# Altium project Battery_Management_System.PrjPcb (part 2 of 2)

## Sheet MCU_ADC.SchDoc
size 431 x 279 mm; Date: Not shown in title block; ApprovedBy: Not shown in title block; CheckedBy: Not shown in title block; Author: Not shown in title block; CompanyName: Not shown in title block; Engineer: Not shown in title block; Organization: Not shown in title block; Address1: Not shown in title block; Address2: Not shown in title block; Address3: Not shown in title block; Address4: Not shown in title block; DocumentNumber: 1; Revision: Use project parameter SCH_Rev; SheetNumber: 5; SheetTotal: 8; PageSetup: Record=PageOptions¦CenterHorizontal=True¦CenterVertical=True¦PrintScale=1.00¦XCorrection=1.00¦YCorrection=1.00¦PrintKind=0¦BorderSize=5000000¦LeftOffset=0¦BottomOffset=0¦Orientation=2¦PaperLength=1000¦PaperWidth=1000¦Scale=100¦PaperSource=15¦PrintQuality=600¦MediaType=1¦DitherType=10¦PaperKind=Letter¦PrintScaleMode=1
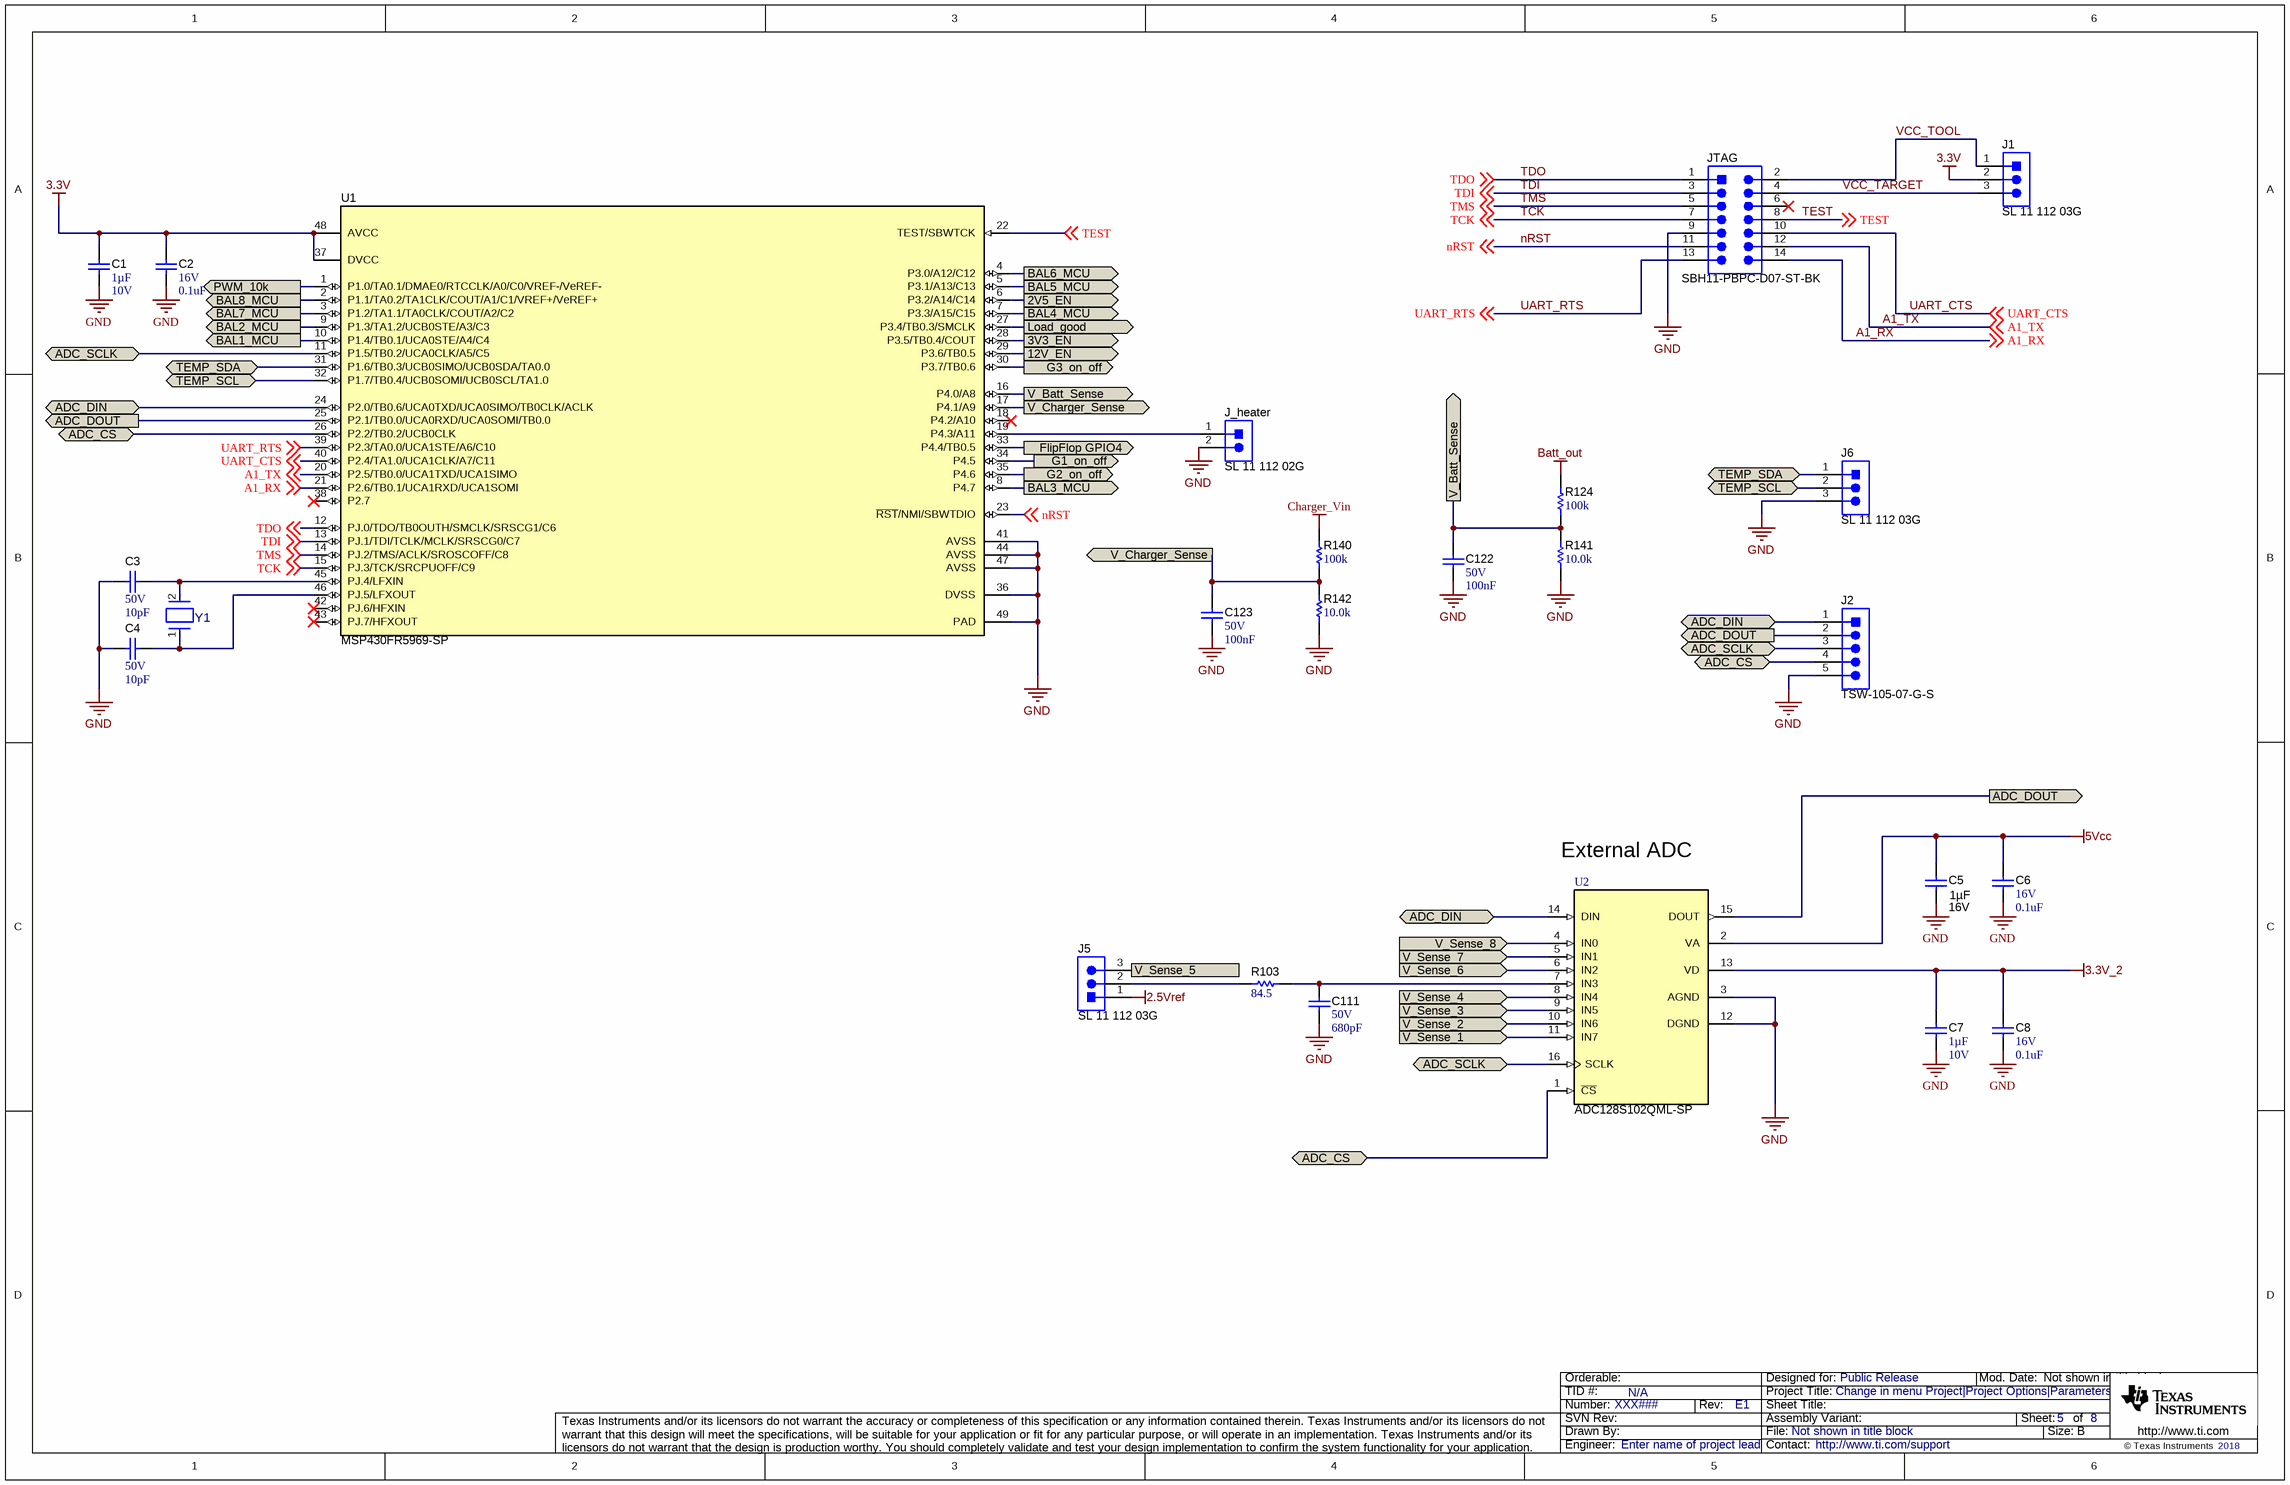
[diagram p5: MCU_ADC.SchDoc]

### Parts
C1  Cap_F: 1µF  VDC_V: 10V  [0805_HV]  (hidden comment: C0805C105K8RACTU)
C2  VDC_V: 16V  ValueDisplayed: 0.1uF  [0805_HV]  (hidden comment: ECPU1C104MA5)
C3  VDC_V: 50V  ValueDisplayed: 10pF  [0603]  (hidden comment: C0603C100J5GACTU)
C4  VDC_V: 50V  ValueDisplayed: 10pF  [0603]  (hidden comment: C0603C100J5GACTU)
C5  Cap_F: 1µF  VDC_V: 16V  [0603]  (hidden comment: CGA3E1X7R1C105K080AC)
C6  VDC_V: 16V  ValueDisplayed: 0.1uF  [0805_HV]  (hidden comment: ECPU1C104MA5)
C7  Cap_F: 1µF  VDC_V: 10V  [0805_HV]  (hidden comment: C0805C105K8RACTU)
C8  VDC_V: 16V  ValueDisplayed: 0.1uF  [0805_HV]  (hidden comment: ECPU1C104MA5)
C111  VDC_V: 50V  ValueDisplayed: 680pF  [0603]  (hidden comment: 06035A681FAT2A)
C122  VDC_V: 50V  Cap_F: 100nF  [0805_HV]  (hidden comment: 08055C104KAT2A)
C123  VDC_V: 50V  Cap_F: 100nF  [0805_HV]  (hidden comment: 08055C104KAT2A)
J1  SL 11 112 03G  [Fischer_SL-11-112-03G]
J2  TSW-105-07-G-S  [TSW-105-07-X-S]
J5  SL 11 112 03G  [Fischer_SL-11-112-03G]
J6  SL 11 112 03G  [Fischer_SL-11-112-03G]
J_heater  SL 11 112 02G  [Fischer_SL-11-112-02G]
JTAG  SBH11-PBPC-D07-ST-BK  [CONN_SBH11-PBPC-D07-ST-BK]
R103  ValueDisplayed: 84.5  [0603]  (hidden comment: RC0603FR-0784R5L)
R124  ValueDisplayed: 100k  [0805_HV]  (hidden comment: RG2012P-104-B-T5)
R140  ValueDisplayed: 100k  [0805_HV]  (hidden comment: RG2012P-104-B-T5)
R141  ValueDisplayed: 10.0k  [0805_HV]  (hidden comment: RG2012P-103-B-T5)
R142  ValueDisplayed: 10.0k  [0805_HV]  (hidden comment: RG2012P-103-B-T5)
U1  PartNumber: MSP430FR5969-SP  [RGZ0048B_NV]  (hidden comment: MSP430FR59691IRGZR)
U2  PartNumber: ADC128S102QML-SP  [NAC0016A_N]  (hidden comment: ADC128S102WGRQV)
Y1  ECS-.327-9-34QCS-TR  [FP-ECS-.327-9-34QCS-TR_SMT_CRYSTAL_3MM2_1MM5-MFG]  (value not drawn)

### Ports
2V5_EN (out), 3V3_EN (out), 12V_EN (out), ADC_CS (bidir), ADC_DIN (bidir), ADC_DOUT (out), ADC_SCLK (bidir), BAL1_MCU (out), BAL2_MCU (out), BAL3_MCU (out), BAL4_MCU (out), BAL5_MCU (out), BAL6_MCU (out), BAL7_MCU (out), BAL8_MCU (out), FlipFlop GPIO4 (out), G1_on_off (out), G2_on_off (out), G3_on_off (out), Load_good (out), PWM_10k (out), TEMP_SCL (bidir), TEMP_SDA (bidir), V_Batt_Sense (out), V_Charger_Sense (out), V_Sense_1 (in), V_Sense_2 (in), V_Sense_3 (in), V_Sense_4 (in), V_Sense_5 (in), V_Sense_6 (in), V_Sense_7 (in), V_Sense_8 (in)

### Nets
2.5Vref: J5.1
3.3V: C1.1 C2.1 J1.2 U1.37(DVCC) U1.48(AVCC)
3.3V_2: C7.1 C8.1 U2.13(VD)
5Vcc: C5.1 C6.1 U2.2(VA)
Batt_out: R124.2
Charger_Vin: R140.2
GND: C1.2 C2.2 C3.2 C4.2 C5.2 C6.2 C7.2 C8.2 C111.2 C122.2 C123.2 J2.5 J6.3 J_heater.2 JTAG.9 R141.1 R142.1 U1.36(DVSS) U1.41(AVSS) U1.44(AVSS) U1.47(AVSS) U1.49(PAD) U2.3(AGND) U2.12(DGND)
2V5_EN: U1.6(P3.2/A14/C14) ; port 2V5_EN
3V3_EN: U1.28(P3.5/TB0.4/COUT) ; port 3V3_EN
12V_EN: U1.29(P3.6/TB0.5) ; port 12V_EN
A1_RX: JTAG.14 U1.21(P2.6/TB0.1/UCA1RXD/UCA1SOMI) ; off-sheet A1_RX
A1_TX: JTAG.12 U1.20(P2.5/TB0.0/UCA1TXD/UCA1SIMO) ; off-sheet A1_TX
ADC_CS: J2.4 U1.26(P2.2/TB0.2/UCB0CLK) U2.1(~{CS}) ; port ADC_CS
ADC_DIN: J2.1 U1.24(P2.0/TB0.6/UCA0TXD/UCA0SIMO/TB0CLK/ACLK) U2.14(DIN) ; port ADC_DIN
ADC_DOUT: J2.2 U1.25(P2.1/TB0.0/UCA0RXD/UCA0SOMI/TB0.0) U2.15(DOUT) ; port ADC_DOUT
ADC_SCLK: J2.3 U1.11(P1.5/TB0.2/UCA0CLK/A5/C5) U2.16(SCLK) ; port ADC_SCLK
BAL1_MCU: U1.10(P1.4/TB0.1/UCA0STE/A4/C4) ; port BAL1_MCU
BAL2_MCU: U1.9(P1.3/TA1.2/UCB0STE/A3/C3) ; port BAL2_MCU
BAL3_MCU: U1.8(P4.7) ; port BAL3_MCU
BAL4_MCU: U1.7(P3.3/A15/C15) ; port BAL4_MCU
BAL5_MCU: U1.5(P3.1/A13/C13) ; port BAL5_MCU
BAL6_MCU: U1.4(P3.0/A12/C12) ; port BAL6_MCU
BAL7_MCU: U1.3(P1.2/TA1.1/TA0CLK/COUT/A2/C2) ; port BAL7_MCU
BAL8_MCU: U1.2(P1.1/TA0.2/TA1CLK/COUT/A1/C1/VREF+/VeREF+) ; port BAL8_MCU
FlipFlop GPIO4: U1.33(P4.4/TB0.5) ; port FlipFlop GPIO4
G1_on_off: U1.34(P4.5) ; port G1_on_off
G2_on_off: U1.35(P4.6) ; port G2_on_off
G3_on_off: U1.30(P3.7/TB0.6) ; port G3_on_off
Load_good: U1.27(P3.4/TB0.3/SMCLK) ; port Load_good
nRST: JTAG.11 U1.23(~{RST}/NMI/SBWTDIO) ; off-sheet nRST
PWM_10k: U1.1(P1.0/TA0.1/DMAE0/RTCCLK/A0/C0/VREF-/VeREF-) ; port PWM_10k
TCK: JTAG.7 U1.15(PJ.3/TCK/SRCPUOFF/C9) ; off-sheet TCK
TDI: JTAG.3 U1.13(PJ.1/TDI/TCLK/MCLK/SRSCG0/C7) ; off-sheet TDI
TDO: JTAG.1 U1.12(PJ.0/TDO/TB0OUTH/SMCLK/SRSCG1/C6) ; off-sheet TDO
TEMP_SCL: J6.2 U1.32(P1.7/TB0.4/UCB0SOMI/UCB0SCL/TA1.0) ; port TEMP_SCL
TEMP_SDA: J6.1 U1.31(P1.6/TB0.3/UCB0SIMO/UCB0SDA/TA0.0) ; port TEMP_SDA
TEST: JTAG.8 U1.22(TEST/SBWTCK) ; off-sheet TEST
TMS: JTAG.5 U1.14(PJ.2/TMS/ACLK/SROSCOFF/C8) ; off-sheet TMS
UART_CTS: JTAG.10 U1.40(P2.4/TA1.0/UCA1CLK/A7/C11) ; off-sheet UART_CTS
UART_RTS: JTAG.13 U1.39(P2.3/TA0.0/UCA1STE/A6/C10) ; off-sheet UART_RTS
V_Batt_Sense: C122.1 R124.1 R141.2 U1.16(P4.0/A8) ; port V_Batt_Sense
V_Charger_Sense: C123.1 R140.1 R142.2 U1.17(P4.1/A9) ; port V_Charger_Sense
V_Sense_1: U2.11(IN7) ; port V_Sense_1
V_Sense_2: U2.10(IN6) ; port V_Sense_2
V_Sense_3: U2.9(IN5) ; port V_Sense_3
V_Sense_4: U2.8(IN4) ; port V_Sense_4
V_Sense_5: J5.3 ; port V_Sense_5
V_Sense_6: U2.6(IN2) ; port V_Sense_6
V_Sense_7: U2.5(IN1) ; port V_Sense_7
V_Sense_8: U2.4(IN0) ; port V_Sense_8
VCC_TARGET: J1.3 JTAG.4
VCC_TOOL: J1.1 JTAG.2
NetC3_1: C3.1 U1.45(PJ.4/LFXIN) Y1.2(Out/In)
NetC4_1: C4.1 U1.46(PJ.5/LFXOUT) Y1.1(In/Out)
NetC111_1: C111.1 R103.2 U2.7(IN3)
NetJ5_2: J5.2 R103.1
NetJ_heater_1: J_heater.1 U1.19(P4.3/A11)

Not connected (* = marked no-connect by the designer): JTAG 6*; U1 18(P4.2/A10)* 38(P2.7)* 42(PJ.6/HFXIN)* 43(PJ.7/HFXOUT)*

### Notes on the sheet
- External ADC

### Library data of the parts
C1 C7 = CMP-0007731-1: CAP, CERM, 1 uF, 10 V, +/- 10%, X7R, 0805; Manufacturer: Kemet; TaMin_C: -55°C; ESR_ohm: 15m; Polarized: N; SizeAreaWB_mm2: 6.75; Value1: 0.015 ohm; U/M: EA; Value: 1uF; TaMax_C: 125°C; SizeZ_mm: 1.45; SizeX_mm: 2; SizeY_mm: 1.25; Cap_Case: 0805; SizeArea_mm2: 2.5; IRMS_A: 8.19A; AEC Category: Q200
C2 C6 C8 = CMP-0012474-2: CAP, Film, 0.1 uF, 16 V, +/- 20%, 0805 SMD; Manufacturer: Panasonic; TaMin_C: -40°C; Polarized: N; SizeAreaWB_mm2: 6.75; Value1: Unknown; U/M: EA; Value: 0.1uF; TaMax_C: 85°C; SizeZ_mm: 1.45; SizeX_mm: 2; SizeY_mm: 1.25; Cap_Case: 0805; SizeArea_mm2: 2.5; Cap_F: 100nF; AEC Category: Q200
C3 C4 = CMP-0006839-1: CAP, CERM, 10 pF, 50 V, +/- 5%, C0G/NP0, 0603; Manufacturer: Kemet; TaMin_C: -55°C; Polarized: N; SizeAreaWB_mm2: 4.68; Value1: Unknown; U/M: EA; Value: 10pF; TaMax_C: 125°C; SizeZ_mm: 1; SizeX_mm: 1.6; SizeY_mm: 0.8; SizeArea_mm2: 1.28; AEC Category: Q200
C5 = CMP-0079607-1: CAP, CERM, 1 µF, 16 V,+/- 10%, X7R, AEC-Q200 Grade 1, 0603; Manufacturer: TDK; TaMin_C: -55°C; Polarized: N; SizeAreaWB_mm2: 4.68; U/M: EA; Value: 1uF; TaMax_C: 125°C; SizeZ_mm: 1; SizeX_mm: 1.6; SizeY_mm: 0.8; SizeArea_mm2: 1.28; AEC Qualified: Y; AEC Category: Q200
C111 = CMP-0006797-3: CAP, CERM, 680 pF, 50 V, +/- 1%, C0G/NP0, 0603; Manufacturer: AVX; TaMin_C: -55°C; Polarized: N; SizeAreaWB_mm2: 4.68; Value1: Unknown; U/M: EA; Value: 680pF; TaMax_C: 125°C; SizeZ_mm: 1; SizeX_mm: 1.6; SizeY_mm: 0.8; SizeArea_mm2: 1.28; AEC Category: Q200
C122 C123 = CMP-0007632-1: CAP, CERM, 0.1 uF, 50 V, +/- 10%, X7R, 0805; Manufacturer: AVX; TaMin_C: -55°C; ESR_ohm: 24m; Polarized: N; SizeAreaWB_mm2: 6.75; Value1: 0.024 ohm; U/M: EA; Value: 0.1uF; TaMax_C: 125°C; SizeZ_mm: 1.45; SizeX_mm: 2; SizeY_mm: 1.25; Cap_Case: 0805; SizeArea_mm2: 2.5; AEC Category: Q200
J1 J5 J6 = CMP-0075048-1: Header, 2.54mm, 3x1, Gold, TH; Manufacturer: Fischer Elektronik; CT: False; CNHeader: True
J2 = CMP-0075411-1: Header, 100mil, 5x1, Gold, TH; Manufacturer: Samtec; Pitch_mm: 2.54; Cert_VDE: N; Gender: Male; Cert_CSA: Y; Voltage_V: 550V; Green_REACh: Passed; Current_A: 6.3A; CT: False; Green_Lifecycle: Active; Row_Count: 1; CNHeader: True
J_heater = CMP-0075049-1: Header, 2.54mm, 2x1, Gold, TH; Manufacturer: Fischer Elektronik; CT: False; CNHeader: True
JTAG = CMP-0054695-2: Header (shrouded), 100 mil, 7x2, Gold, TH; Manufacturer: Sullins Connector Solutions; Green_REACh: Incomplete; Green_Lifecycle: Not Set
R103 = CMP-0023298-5: RES, 84.5, 1%, 0.1 W, 0603; Manufacturer: Yageo; Power_W: 100mW; TempCo: 100 ppm/C; Value_Code: 84R5; Value: 84.5; EIA_Code: E96; SizeX_mm: 1.6; SizeY_mm: 0.8; SizeZ_mm: 1; Value2: 0.1W; SizeArea_mm2: 1.28; AEC Qualified: N; VDC_V: 75V; AEC Category: Q200; SizeAreaWB_mm2: 4.68
R124 R140 = CMP-0018857-2: RES, 100 k, 0.1%, 0.125 W, 0805; Manufacturer: Susumu Co Ltd; Power_W: 125mW; TempCo: 25 ppm/C; U/M: EA; Value: 100k; EIA_Code: E192; SizeX_mm: 2; SizeY_mm: 1.25; SizeZ_mm: 1.45; Value2: 0.125W; SizeArea_mm2: 2.5; VDC_V: 100V; AEC Category: Q200
R141 R142 = CMP-0018856-2: RES, 10.0 k, 0.1%, 0.125 W, 0805; Manufacturer: Susumu Co Ltd; Power_W: 125mW; TempCo: 25 ppm/C; Value_Code: 10k0; U/M: EA; Value: 10.0k; EIA_Code: E192; Res_ohm: 10k; SizeX_mm: 2; SizeY_mm: 1.25; SizeZ_mm: 1.45; Value2: 0.125W; SizeArea_mm2: 2.5; VDC_V: 100V; AEC Category: Q200
U1 = CMP-0076614-1: MSP430FR59691 16 MHz Ultra-Low-Power Microcontroller featuring 64 KB FRAM, 2 KB SRAM, 40 IO, RGZ0048B (VQFN-48); Manufacturer: Texas Instruments; Alternate PartNumber: MSP430FR59691IRGZT; SizeAreaWB_mm2: 81.0; SizeArea_mm2: 49.0; SizeZ_mm: 1.0; SizeY_mm: 7.0; U/M: EA; CompType: IC
U2 = CMP-0067762-2: 3V LVDS Quad CMOS Differential Line Driver, NAC0016A (CFP-16); Manufacturer: Texas Instruments; CompType: ADC IC; High-Reliability: Y; AEC Category: Q200; AEC Qualified: N; SizeAreaWB_mm2: 295.5; SizeArea_mm2: 103.2; SizeX_mm: 10.41; SizeY_mm: 9.91; SizeZ_mm: 2.33
Y1 = CMP-0089623-1: 32.768kHz ±10ppm Crystal 9pF 80 kOhms 2-SMD, No Lead , Automotive AEC-Q200; Manufacturer: ECS Inc.; AEC Grade: Grade 1; Esr: 70k; SizeZ_mm: 0.9mm; AEC Qualified: Yes

## Sheet Balancer.SchDoc
size 431 x 279 mm; Date: Not shown in title block; ApprovedBy: Not shown in title block; CheckedBy: Not shown in title block; Author: Not shown in title block; CompanyName: Not shown in title block; Engineer: Not shown in title block; Organization: Not shown in title block; Address1: Not shown in title block; Address2: Not shown in title block; Address3: Not shown in title block; Address4: Not shown in title block; DocumentNumber: 1; Revision: Use project parameter SCH_Rev; SheetNumber: 6; SheetTotal: 8; PageSetup: Record=PageOptions¦CenterHorizontal=True¦CenterVertical=True¦PrintScale=1.00¦XCorrection=1.00¦YCorrection=1.00¦PrintKind=0¦BorderSize=5000000¦LeftOffset=0¦BottomOffset=0¦Orientation=2¦PaperLength=1000¦PaperWidth=1000¦Scale=100¦PaperSource=15¦PrintQuality=600¦MediaType=1¦DitherType=10¦PaperKind=Letter¦PrintScaleMode=1
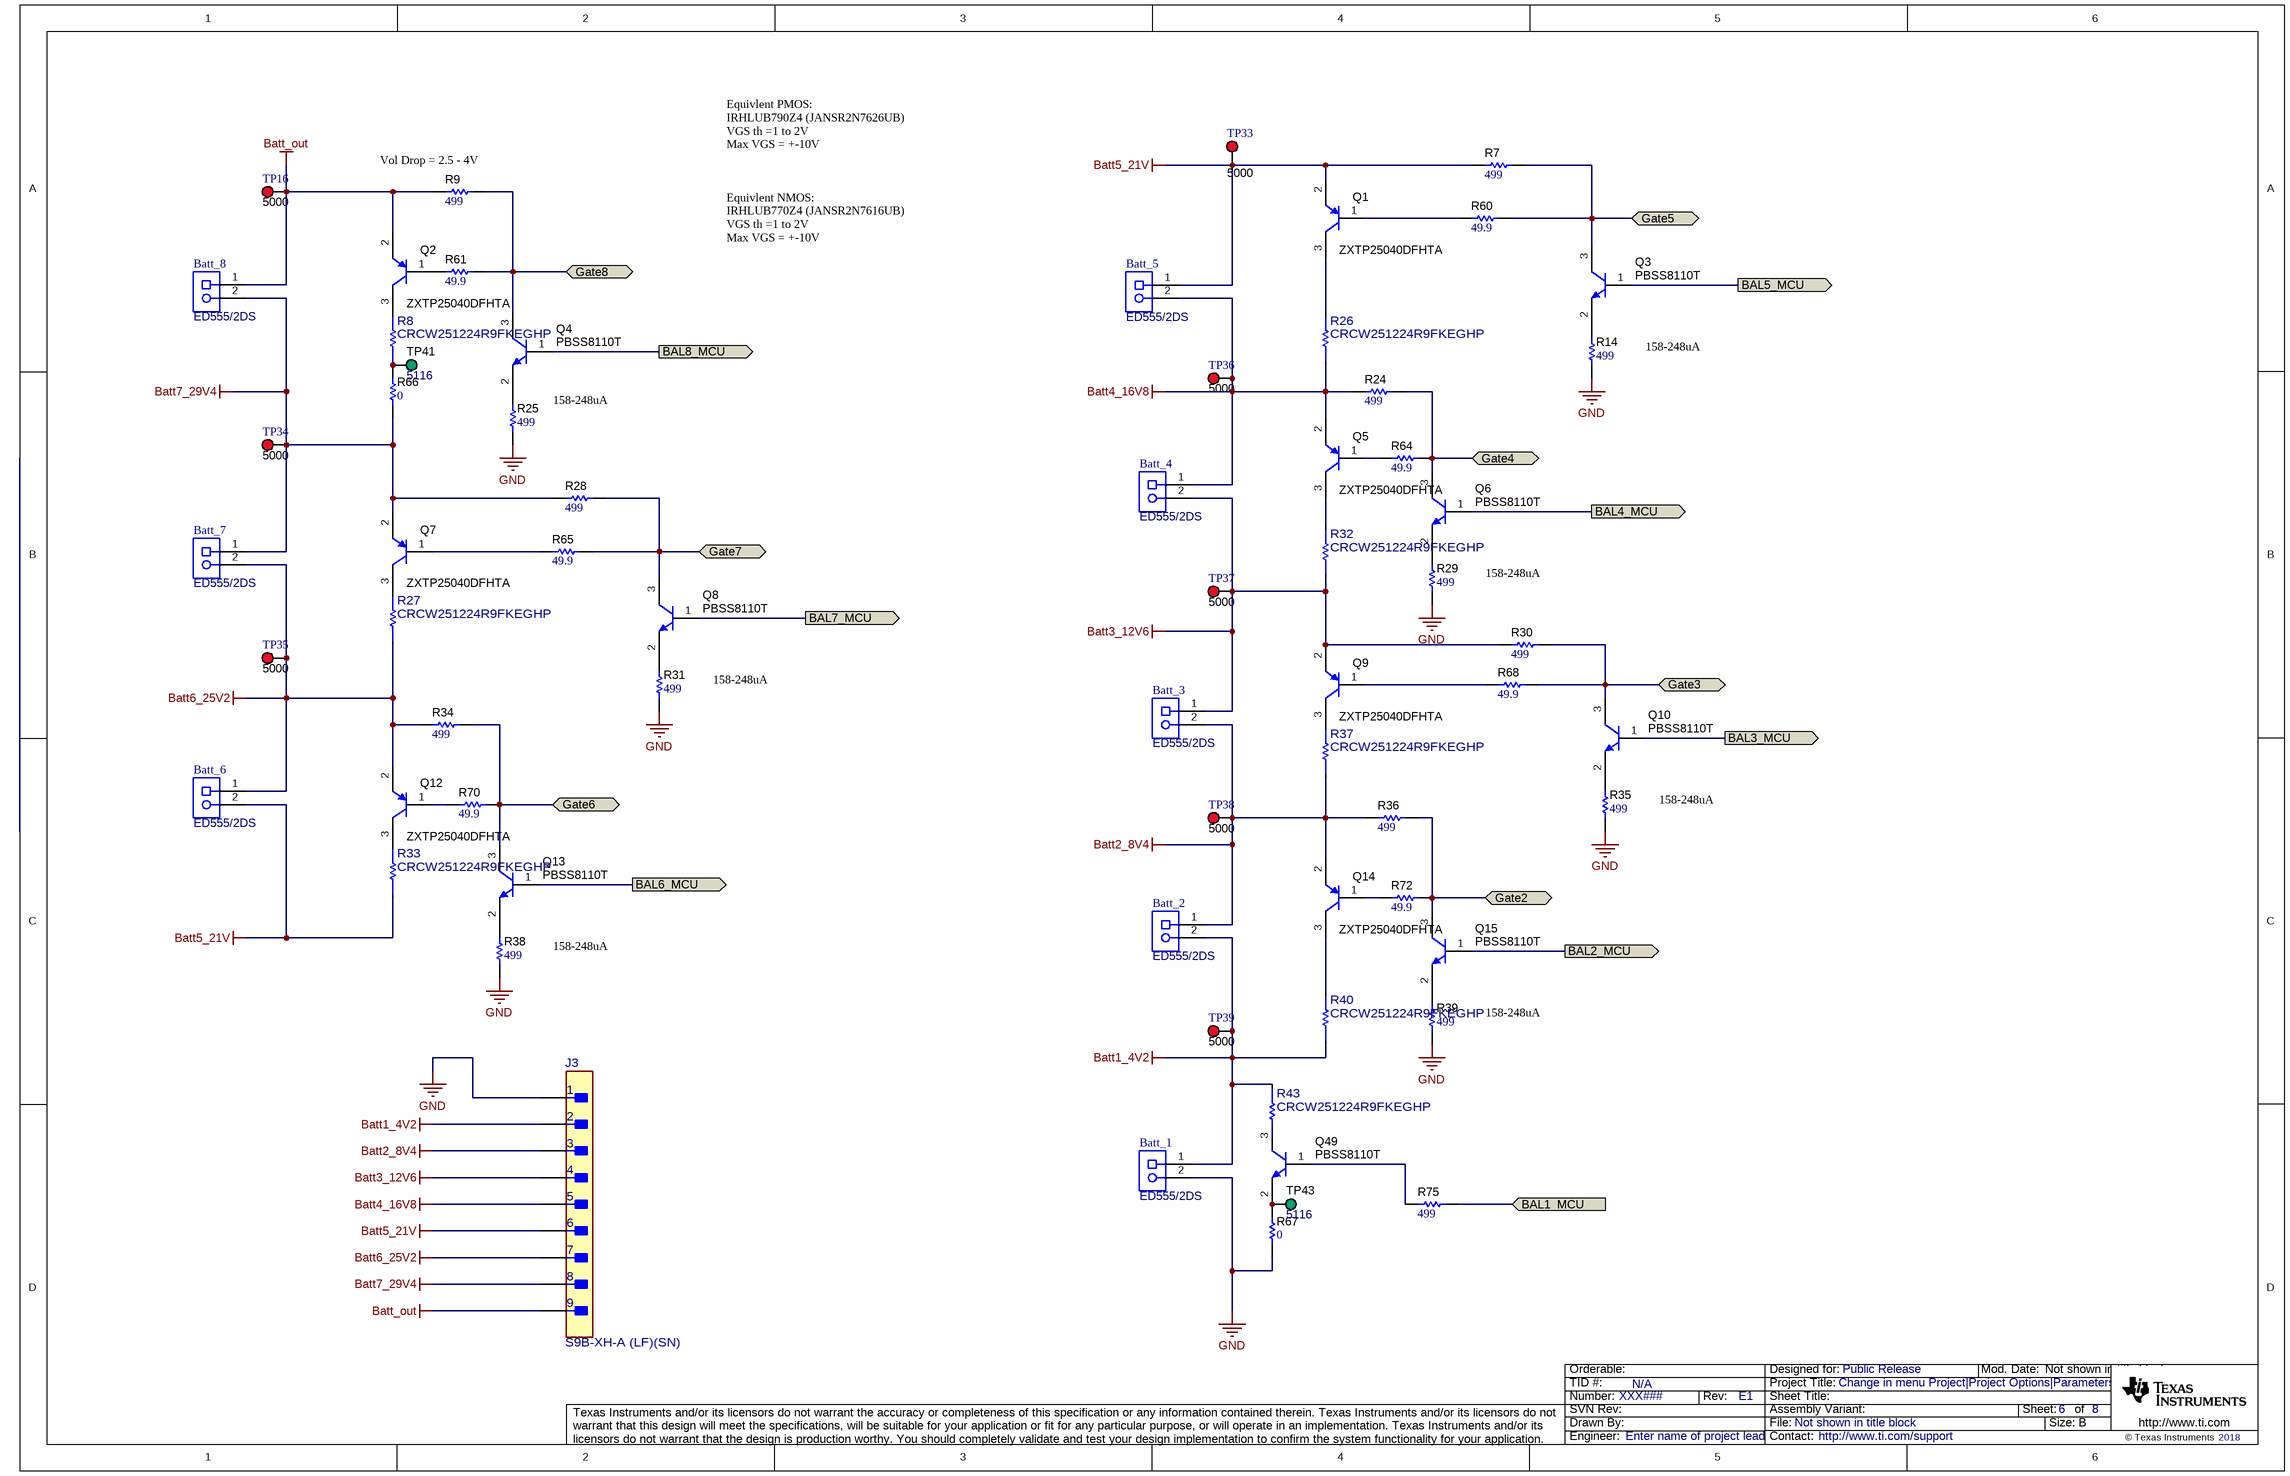
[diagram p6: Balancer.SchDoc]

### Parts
Batt_1  ED555/2DS  [TERM_BLK_ED555-2DS]
Batt_2  ED555/2DS  [TERM_BLK_ED555-2DS]
Batt_3  ED555/2DS  [TERM_BLK_ED555-2DS]
Batt_4  ED555/2DS  [TERM_BLK_ED555-2DS]
Batt_5  ED555/2DS  [TERM_BLK_ED555-2DS]
Batt_6  ED555/2DS  [TERM_BLK_ED555-2DS]
Batt_7  ED555/2DS  [TERM_BLK_ED555-2DS]
Batt_8  ED555/2DS  [TERM_BLK_ED555-2DS]
J3  S9B-XH-A (LF)(SN)  [FP-S9B-XH-A (LF)(SN)_CONN_FFC_9P-MFG]
Q1  ZXTP25040DFHTA  [SOT-23]
Q2  ZXTP25040DFHTA  [SOT-23]
Q3  PBSS8110T  [SOT-23]
Q4  PBSS8110T  [SOT-23]
Q5  ZXTP25040DFHTA  [SOT-23]
Q6  PBSS8110T  [SOT-23]
Q7  ZXTP25040DFHTA  [SOT-23]
Q8  PBSS8110T  [SOT-23]
Q9  ZXTP25040DFHTA  [SOT-23]
Q10  PBSS8110T  [SOT-23]
Q12  ZXTP25040DFHTA  [SOT-23]
Q13  PBSS8110T  [SOT-23]
Q14  ZXTP25040DFHTA  [SOT-23]
Q15  PBSS8110T  [SOT-23]
Q49  PBSS8110T  [SOT-23]
R7  ValueDisplayed: 499  [0805_HV]  (hidden comment: CRCW0805499RFKEA)
R8  CRCW251224R9FKEGHP  [FP-CRCW251224R9FKEGHP_2512-MFG]
R9  ValueDisplayed: 499  [0805_HV]  (hidden comment: CRCW0805499RFKEA)
R14  ValueDisplayed: 499  [0805_HV]  (hidden comment: CRCW0805499RFKEA)
R24  ValueDisplayed: 499  [0805_HV]  (hidden comment: CRCW0805499RFKEA)
R25  ValueDisplayed: 499  [0805_HV]  (hidden comment: CRCW0805499RFKEA)
R26  CRCW251224R9FKEGHP  [FP-CRCW251224R9FKEGHP_2512-MFG]
R27  CRCW251224R9FKEGHP  [FP-CRCW251224R9FKEGHP_2512-MFG]
R28  ValueDisplayed: 499  [0805_HV]  (hidden comment: CRCW0805499RFKEA)
R29  ValueDisplayed: 499  [0805_HV]  (hidden comment: CRCW0805499RFKEA)
R30  ValueDisplayed: 499  [0805_HV]  (hidden comment: CRCW0805499RFKEA)
R31  ValueDisplayed: 499  [0805_HV]  (hidden comment: CRCW0805499RFKEA)
R32  CRCW251224R9FKEGHP  [FP-CRCW251224R9FKEGHP_2512-MFG]
R33  CRCW251224R9FKEGHP  [FP-CRCW251224R9FKEGHP_2512-MFG]
R34  ValueDisplayed: 499  [0805_HV]  (hidden comment: CRCW0805499RFKEA)
R35  ValueDisplayed: 499  [0805_HV]  (hidden comment: CRCW0805499RFKEA)
R36  ValueDisplayed: 499  [0805_HV]  (hidden comment: CRCW0805499RFKEA)
R37  CRCW251224R9FKEGHP  [FP-CRCW251224R9FKEGHP_2512-MFG]
R38  ValueDisplayed: 499  [0805_HV]  (hidden comment: CRCW0805499RFKEA)
R39  ValueDisplayed: 499  [0805_HV]  (hidden comment: CRCW0805499RFKEA)
R40  CRCW251224R9FKEGHP  [FP-CRCW251224R9FKEGHP_2512-MFG]
R43  CRCW251224R9FKEGHP  [FP-CRCW251224R9FKEGHP_2512-MFG]
R60  ValueDisplayed: 49.9  [0805_HV]  (hidden comment: M55342K06B49D9T)
R61  ValueDisplayed: 49.9  [0805_HV]  (hidden comment: M55342K06B49D9T)
R64  ValueDisplayed: 49.9  [0805_HV]  (hidden comment: M55342K06B49D9T)
R65  ValueDisplayed: 49.9  [0805_HV]  (hidden comment: M55342K06B49D9T)
R66  ValueDisplayed: 0  [0805_HV]  (hidden comment: MCR10EZHJ000)
R67  ValueDisplayed: 0  [0805_HV]  (hidden comment: MCR10EZHJ000)
R68  ValueDisplayed: 49.9  [0805_HV]  (hidden comment: M55342K06B49D9T)
R70  ValueDisplayed: 49.9  [0805_HV]  (hidden comment: M55342K06B49D9T)
R72  ValueDisplayed: 49.9  [0805_HV]  (hidden comment: M55342K06B49D9T)
R75  ValueDisplayed: 499  [0805_HV]  (hidden comment: CRCW0805499RFKEA)
TP16  5000  [Keystone5000]
TP33  5000  [Keystone5000]
TP34  5000  [Keystone5000]
TP35  5000  [Keystone5000]
TP36  5000  [Keystone5000]
TP37  5000  [Keystone5000]
TP38  5000  [Keystone5000]
TP39  5000  [Keystone5000]
TP41  5116  [Keystone_5116]
TP43  5116  [Keystone_5116]

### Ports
BAL1_MCU (in), BAL2_MCU (out), BAL3_MCU (out), BAL4_MCU (out), BAL5_MCU (out), BAL6_MCU (out), BAL7_MCU (out), BAL8_MCU (out), Gate2 (bidir), Gate3 (bidir), Gate4 (bidir), Gate5 (bidir), Gate6 (bidir), Gate7 (bidir), Gate8 (bidir)

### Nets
Batt1_4V2: Batt_1.1 Batt_2.2 J3.2 R40.1 R43.2 TP39.1
Batt2_8V4: Batt_2.1 Batt_3.2 J3.3 Q14.2(E) R36.1 R37.1 TP38.1
Batt3_12V6: Batt_3.1 Batt_4.2 J3.4 Q9.2(E) R30.1 R32.1 TP37.1
Batt4_16V8: Batt_4.1 Batt_5.2 J3.5 Q5.2(E) R24.1 R26.1 TP36.1
Batt5_21V: Batt_5.1 Batt_6.2 J3.6 Q1.2(E) R7.1 R33.1 TP33.1
Batt6_25V2: Batt_6.1 Batt_7.2 J3.7 Q12.2(E) R27.1 R34.1 TP35.1
Batt7_29V4: Batt_7.1 Batt_8.2 J3.8 Q7.2(E) R28.1 R66.2 TP34.1
Batt_out: Batt_8.1 J3.9 Q2.2(E) R9.1 TP16.1
GND: Batt_1.2 J3.1 R14.1 R25.1 R29.1 R31.1 R35.1 R38.1 R39.1 R67.2
BAL1_MCU: R75.2 ; port BAL1_MCU
BAL2_MCU: Q15.1(B) ; port BAL2_MCU
BAL3_MCU: Q10.1(B) ; port BAL3_MCU
BAL4_MCU: Q6.1(B) ; port BAL4_MCU
BAL5_MCU: Q3.1(B) ; port BAL5_MCU
BAL6_MCU: Q13.1(B) ; port BAL6_MCU
BAL7_MCU: Q8.1(B) ; port BAL7_MCU
BAL8_MCU: Q4.1(B) ; port BAL8_MCU
Gate2: Q15.3(C) R36.2 R72.2 ; port Gate2
Gate3: Q10.3(C) R30.2 R68.2 ; port Gate3
Gate4: Q6.3(C) R24.2 R64.2 ; port Gate4
Gate5: Q3.3(C) R7.2 R60.2 ; port Gate5
Gate6: Q13.3(C) R34.2 R70.2 ; port Gate6
Gate7: Q8.3(C) R28.2 R65.2 ; port Gate7
Gate8: Q4.3(C) R9.2 R61.2 ; port Gate8
NetQ1_1: Q1.1(B) R60.1
NetQ1_3: Q1.3(C) R26.2
NetQ2_1: Q2.1(B) R61.1
NetQ2_3: Q2.3(C) R8.2
NetQ3_2: Q3.2(E) R14.2
NetQ4_2: Q4.2(E) R25.2
NetQ5_1: Q5.1(B) R64.1
NetQ5_3: Q5.3(C) R32.2
NetQ6_2: Q6.2(E) R29.2
NetQ7_1: Q7.1(B) R65.1
NetQ7_3: Q7.3(C) R27.2
NetQ8_2: Q8.2(E) R31.2
NetQ9_1: Q9.1(B) R68.1
NetQ9_3: Q9.3(C) R37.2
NetQ10_2: Q10.2(E) R35.2
NetQ12_1: Q12.1(B) R70.1
NetQ12_3: Q12.3(C) R33.2
NetQ13_2: Q13.2(E) R38.2
NetQ14_1: Q14.1(B) R72.1
NetQ14_3: Q14.3(C) R40.2
NetQ15_2: Q15.2(E) R39.2
NetQ49_1: Q49.1(B) R75.1
NetQ49_2: Q49.2(E) R67.1 TP43.1
NetQ49_3: Q49.3(C) R43.1
NetR8_1: R8.1 R66.1 TP41.1

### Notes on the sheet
- (near R9) Vol Drop = 2.5 - 4V
- Equivlent PMOS:
  IRHLUB790Z4 (JANSR2N7626UB)
  VGS th =1 to 2V
  Max VGS = +-10V
- Equivlent NMOS:
  IRHLUB770Z4 (JANSR2N7616UB)
  VGS th =1 to 2V
  Max VGS = +-10V
- 158-248uA

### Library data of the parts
Batt_1-Batt_8 = CMP-0074913-1: Terminal Block, 3.5mm Pitch, 2x1, TH; Manufacturer: On-Shore Technology; Cert_VDE: Y; CNHeader: False; Current_A: 6A; Green_Lifecycle: Active; Shrouded: N; Gender: Female; Green_REACh: Passed; Voltage_V: 150V; Row_Count: 1; Pitch_mm: 3.5; ContactFinish: Brass; CT: True
J3 = CMP-0097746-1: Connector Header Through Hole, Right Angle 9 position 0.098" (2.50mm); Manufacturer: JST; DUT-Pitch_mm: 2.5mm; Current_A: 3A; Conn Gender: Male; Row_Count: 1; SizeZ_mm: 6.1mm; Is Female: yes; AEC Qualified: No; Voltage_V: 250V; ContactFinish: Tin,Copper
Q1 Q2 Q5 Q7 Q9 Q12 Q14 = CMP-0000353-2: Transistor, PNP, 40 V, 3 A, SOT-23; Manufacturer: Diodes Inc.; TaMax_C: 150°C; Value2: 900; Value1: 3 A; Vcesat1_V: 170mV; SizeX_mm: 2.5; SizeY_mm: 3; TaMin_C: -55°C; IcRated_A: 3A; CompType: BJT; SizeZ_mm: 1.1; AEC Qualified: N; Value: 40 V; SizeArea_mm2: 7.5; NPN: 0; Vceo_V: 40V; PNP: 1; AEC Category: Q101; SizeAreaWB_mm2: 14; U/M: EA
Q3 Q4 Q6 Q8 Q10 Q13 Q15 Q49 = CMP-0000451-1: Transistor, NPN, 100 V, 1 A, SOT-23; Manufacturer: NXP Semiconductor; TaMax_C: 150°C; Value2: 500; Value1: 1 A; Vcesat1_V: 40mV; SizeX_mm: 2.5; SizeY_mm: 3; TaMin_C: -65°C; IcRated_A: 1A; CompType: BJT; SizeZ_mm: 1.1; Value: 100 V; SizeArea_mm2: 7.5; NPN: 1; Vceo_V: 100V; PNP: 0; AEC Category: Q101; SizeAreaWB_mm2: 14; U/M: EA
R7 R9 R14 R24 R25 R28-R31 R34-R36 R38 R39 R75 = CMP-0021282-3: RES, 499, 1%, 0.125 W, AEC-Q200 Grade 0, 0805; Manufacturer: Vishay-Dale; Power_W: 125mW; TempCo: 100 ppm/C; Value_Code: 499R; Value: 499; EIA_Code: E96; SizeX_mm: 2; SizeY_mm: 1.25; SizeZ_mm: 1.45; Value2: 0.125W; SizeArea_mm2: 2.5; AEC Qualified: Y; VDC_V: 150V; AEC Category: Q200; AEC Grade: 0
R8 R26 R27 R32 R33 R37 R40 R43 = CMP-0095213-1: RES Thick Film, 24.9Ω, 1%, 1.5W, 100ppm/°C, 2512; Manufacturer: Vishay Dale; Res_ohm: 24.9; AEC Qualified: Yes; VDC_V: 500V; AEC Grade: Grade 0; Value: 24.9; SizeZ_mm: 0.7mm
R60 R61 R64 R65 R68 R70 R72 = CMP-0079710-1: RES, 49.9, 1%, 0.15 W, 0805; Manufacturer: TT Electronics/IRC; Power_W: 150mW; TempCo: 100 ppm/C; SizeAreaWB_mm2: 6.75; Value_Code: 49R9; Value: 49.9; EIA_Code: E96; SizeX_mm: 2; SizeY_mm: 1.25; SizeZ_mm: 1.45; Value2: 0.15W; SizeArea_mm2: 2.5; AEC Qualified: N; AEC Category: Q200
R66 R67 = CMP-0020801-3: RES, 0, 5%, 0.125 W, 0805; Manufacturer: Rohm; SizeX_mm: 2; Value_Code: 0000; MFG_Status: TI_Obsolete; U/M: EA; SizeZ_mm: 1.45; Power_W: 125mW; Value: 0; TempCo: 400 ppm/C; SizeY_mm: 1.25; EIA_Code: E24; Value2: 0.125W; AEC Category: Q200; VDC_V: 150V; SizeArea_mm2: 2.5
TP16 TP33-TP39 = CMP-0055137-1: Test Point, Miniature, Red, TH; Manufacturer: Keystone; CNHeader: FALSE; Green_Lifecycle: Active; Green_REACh: Passed; ContactFinish: Silver; CT: TRUE
TP41 TP43 = CMP-0055164-1: Test Point, Miniature, Green, TH; Manufacturer: Keystone; CNHeader: FALSE; Green_Lifecycle: Active; Green_REACh: Passed; Row_Count: 1; ContactFinish: Silver; CT: TRUE; Cert_UL: Y

## Sheet Temp Sensing.SchDoc
size 431 x 279 mm; Date: Not shown in title block; ApprovedBy: Not shown in title block; CheckedBy: Not shown in title block; Author: Not shown in title block; CompanyName: Not shown in title block; Engineer: Not shown in title block; Organization: Not shown in title block; Address1: Not shown in title block; Address2: Not shown in title block; Address3: Not shown in title block; Address4: Not shown in title block; DocumentNumber: 1; Revision: Use project parameter SCH_Rev; SheetNumber: 7; SheetTotal: 8; PageSetup: Record=PageOptions¦CenterHorizontal=True¦CenterVertical=True¦PrintScale=1.00¦XCorrection=1.00¦YCorrection=1.00¦PrintKind=0¦BorderSize=5000000¦LeftOffset=0¦BottomOffset=0¦Orientation=2¦PaperLength=1000¦PaperWidth=1000¦Scale=100¦PaperSource=15¦PrintQuality=600¦MediaType=1¦DitherType=10¦PaperKind=Letter¦PrintScaleMode=1
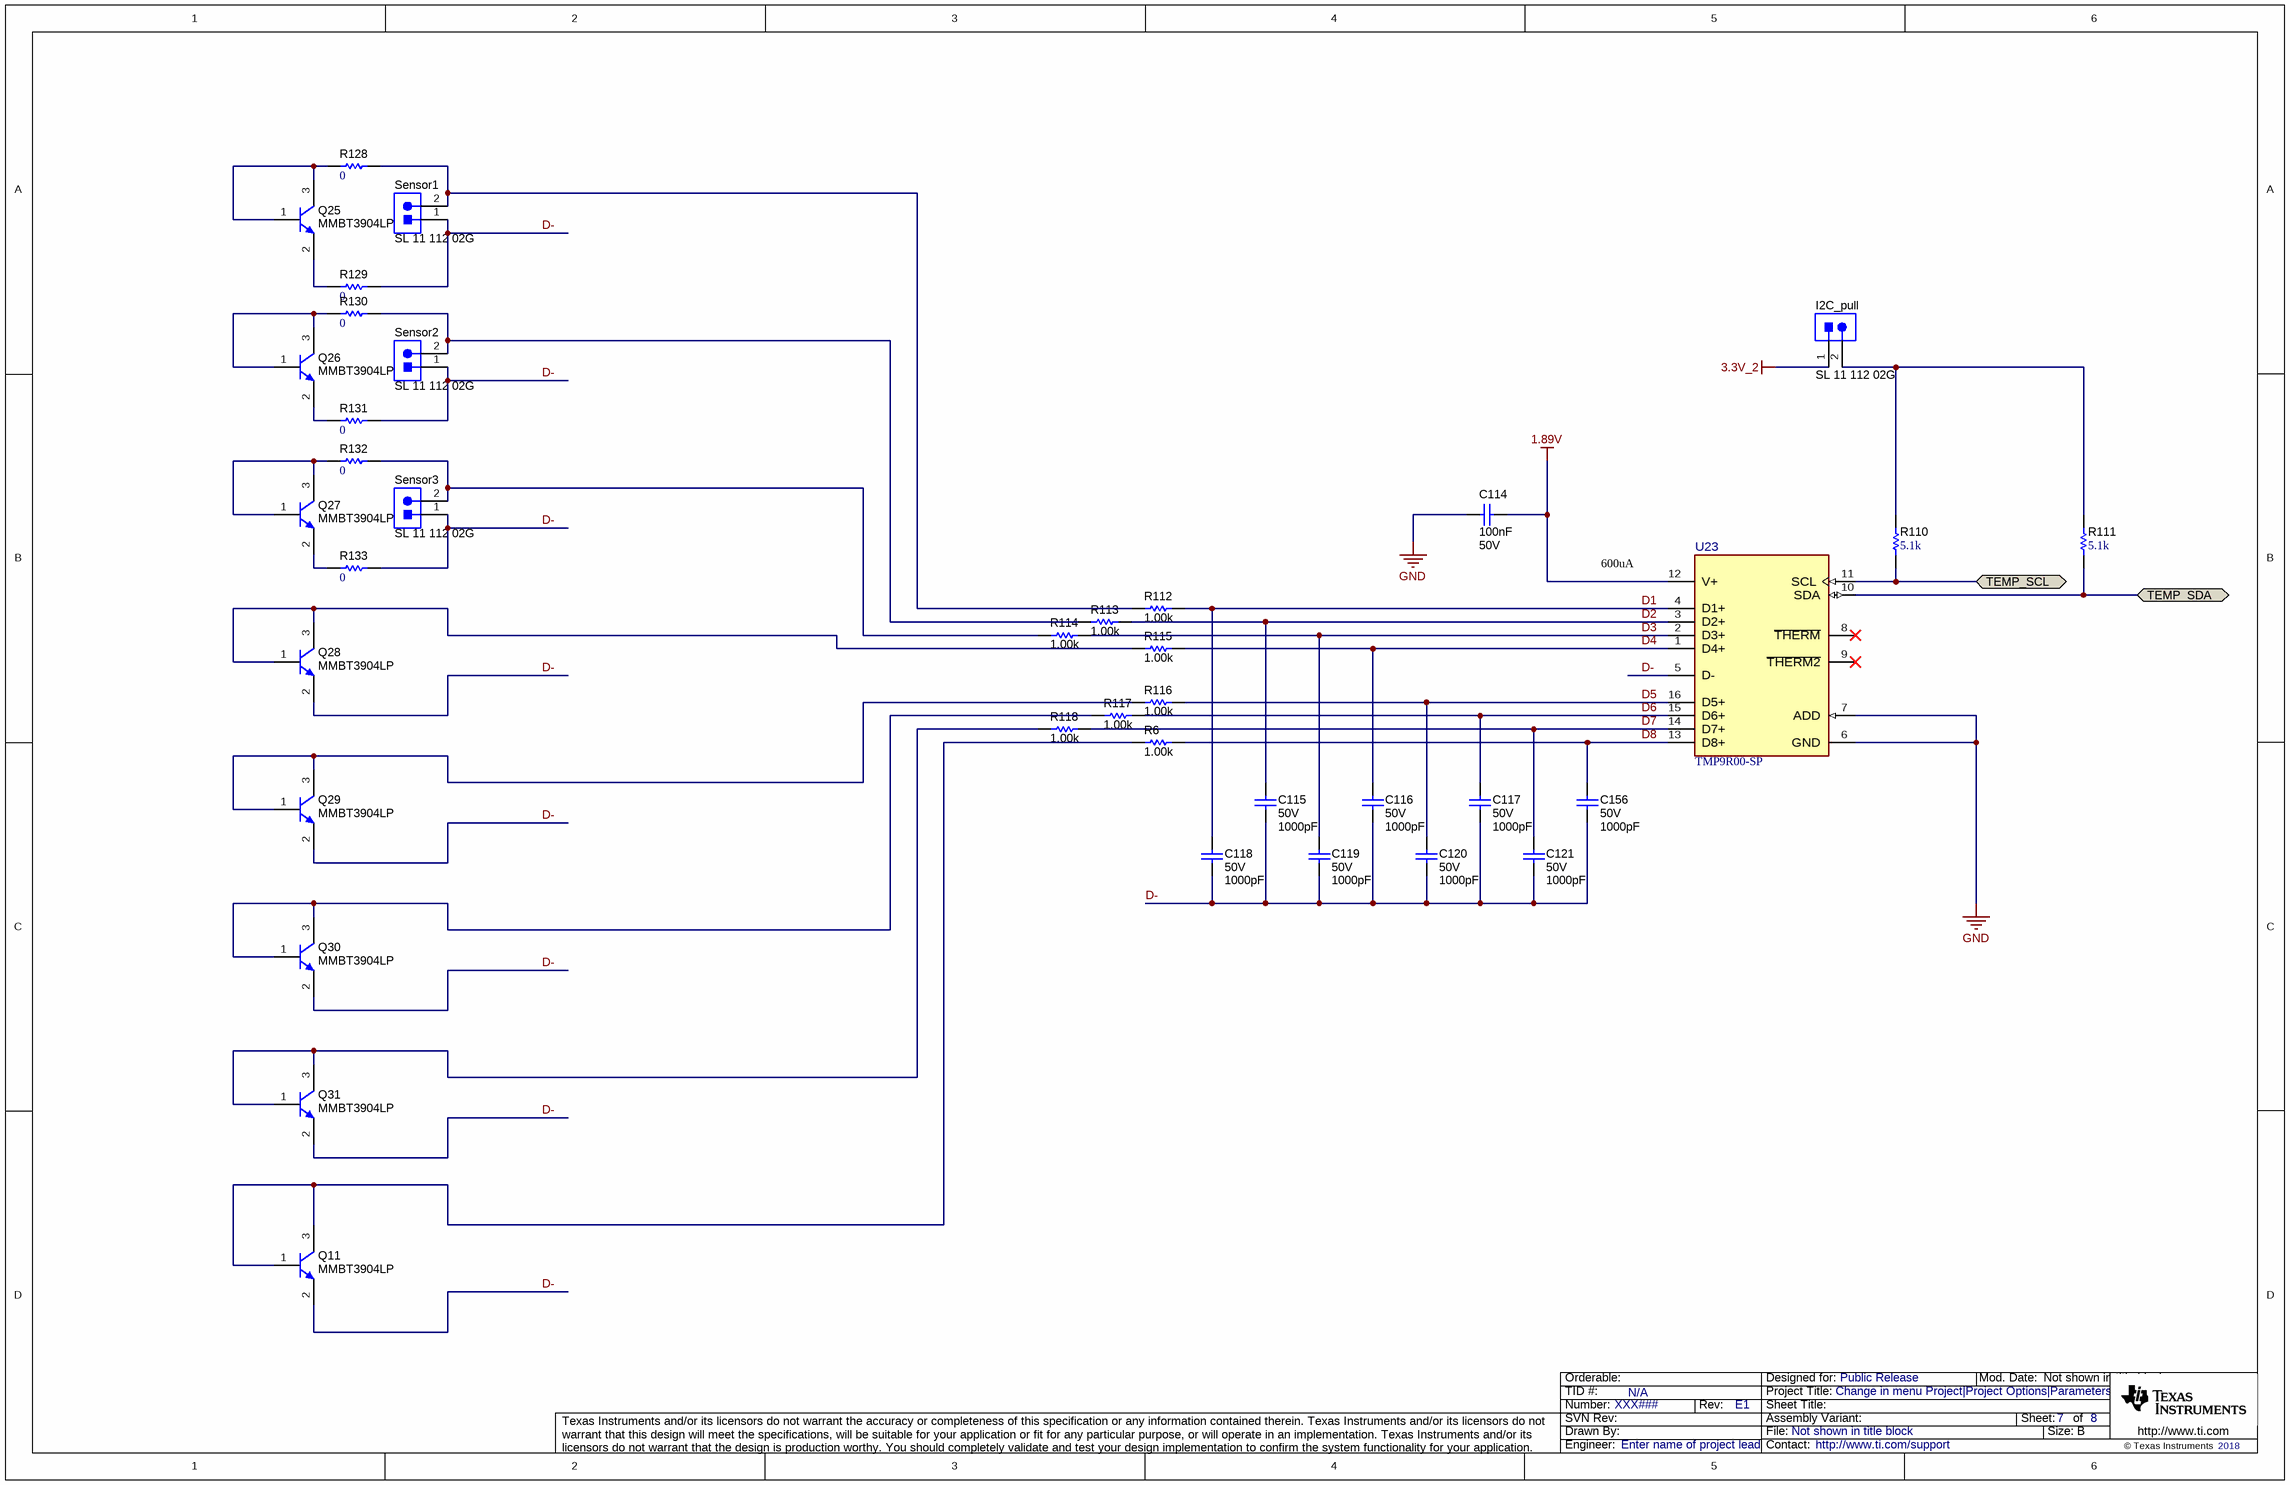
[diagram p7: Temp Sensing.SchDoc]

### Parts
C114  Cap_F: 100nF  VDC_V: 50V  [0603]  (hidden comment: C0603C104K5RACTU)
C115  VDC_V: 50V  ValueDisplayed: 1000pF  [0603]  (hidden comment: C0603C102J5GACTU)
C116  VDC_V: 50V  ValueDisplayed: 1000pF  [0603]  (hidden comment: C0603C102J5GACTU)
C117  VDC_V: 50V  ValueDisplayed: 1000pF  [0603]  (hidden comment: C0603C102J5GACTU)
C118  VDC_V: 50V  ValueDisplayed: 1000pF  [0603]  (hidden comment: C0603C102J5GACTU)
C119  VDC_V: 50V  ValueDisplayed: 1000pF  [0603]  (hidden comment: C0603C102J5GACTU)
C120  VDC_V: 50V  ValueDisplayed: 1000pF  [0603]  (hidden comment: C0603C102J5GACTU)
C121  VDC_V: 50V  ValueDisplayed: 1000pF  [0603]  (hidden comment: C0603C102J5GACTU)
C156  VDC_V: 50V  ValueDisplayed: 1000pF  [0603]  (hidden comment: C0603C102J5GACTU)
I2C_pull  SL 11 112 02G  [Fischer_SL-11-112-02G]
Q11  MMBT3904LP  [DIODES_X1-DFN1006-3]
Q25  MMBT3904LP  [DIODES_X1-DFN1006-3]
Q26  MMBT3904LP  [DIODES_X1-DFN1006-3]
Q27  MMBT3904LP  [DIODES_X1-DFN1006-3]
Q28  MMBT3904LP  [DIODES_X1-DFN1006-3]
Q29  MMBT3904LP  [DIODES_X1-DFN1006-3]
Q30  MMBT3904LP  [DIODES_X1-DFN1006-3]
Q31  MMBT3904LP  [DIODES_X1-DFN1006-3]
R6  ValueDisplayed: 1.00k  [0603]  (hidden comment: RT0603BRD071KL)
R110  ValueDisplayed: 5.1k  [0805_HV]  (hidden comment: ERJ-6GEYJ512V)
R111  ValueDisplayed: 5.1k  [0805_HV]  (hidden comment: ERJ-6GEYJ512V)
R112  ValueDisplayed: 1.00k  [0603]  (hidden comment: RT0603BRD071KL)
R113  ValueDisplayed: 1.00k  [0603]  (hidden comment: RT0603BRD071KL)
R114  ValueDisplayed: 1.00k  [0603]  (hidden comment: RT0603BRD071KL)
R115  ValueDisplayed: 1.00k  [0603]  (hidden comment: RT0603BRD071KL)
R116  ValueDisplayed: 1.00k  [0603]  (hidden comment: RT0603BRD071KL)
R117  ValueDisplayed: 1.00k  [0603]  (hidden comment: RT0603BRD071KL)
R118  ValueDisplayed: 1.00k  [0603]  (hidden comment: RT0603BRD071KL)
R128  ValueDisplayed: 0  [0603]  (hidden comment: MCT06030Z0000ZP500)
R129  ValueDisplayed: 0  [0603]  (hidden comment: MCT06030Z0000ZP500)
R130  ValueDisplayed: 0  [0603]  (hidden comment: MCT06030Z0000ZP500)
R131  ValueDisplayed: 0  [0603]  (hidden comment: MCT06030Z0000ZP500)
R132  ValueDisplayed: 0  [0603]  (hidden comment: MCT06030Z0000ZP500)
R133  ValueDisplayed: 0  [0603]  (hidden comment: MCT06030Z0000ZP500)
Sensor1  SL 11 112 02G  [Fischer_SL-11-112-02G]
Sensor2  SL 11 112 02G  [Fischer_SL-11-112-02G]
Sensor3  SL 11 112 02G  [Fischer_SL-11-112-02G]
U23  PartNumber: TMP9R00-SP  [HKT0016A-IPC_C]  (hidden comment: 5962R2021401VXC)

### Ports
TEMP_SCL (bidir), TEMP_SDA (bidir)

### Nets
1.89V: C114.2 U23.12(V+)
3.3V_2: I2C_pull.1
GND: C114.1 U23.6(GND) U23.7(ADD)
D1: C118.1 R112.2 U23.4(D1+)
D2: C115.1 R113.2 U23.3(D2+)
D3: C119.1 R114.2 U23.2(D3+)
D4: C116.1 R115.2 U23.1(D4+)
D5: C120.1 R116.2 U23.16(D5+)
D6: C117.1 R117.2 U23.15(D6+)
D7: C121.1 R118.2 U23.14(D7+)
D8: C156.1 R6.2 U23.13(D8+)
D-: C115.2 C116.2 C117.2 C118.2 C119.2 C120.2 C121.2 C156.2 Q11.2(E) Q28.2(E) Q29.2(E) Q30.2(E) Q31.2(E) R129.2 R131.2 R133.2 Sensor1.1 Sensor2.1 Sensor3.1 U23.5(D-)
TEMP_SCL: R110.1 U23.11(SCL) ; port TEMP_SCL
TEMP_SDA: R111.1 U23.10(SDA) ; port TEMP_SDA
NetI2C_pull_2: I2C_pull.2 R110.2 R111.2
NetQ11_1: Q11.1(B) Q11.3(C) R6.1
NetQ25_1: Q25.1(B) Q25.3(C) R128.1
NetQ25_2: Q25.2(E) R129.1
NetQ26_1: Q26.1(B) Q26.3(C) R130.1
NetQ26_2: Q26.2(E) R131.1
NetQ27_1: Q27.1(B) Q27.3(C) R132.1
NetQ27_2: Q27.2(E) R133.1
NetQ28_1: Q28.1(B) Q28.3(C) R115.1
NetQ29_1: Q29.1(B) Q29.3(C) R116.1
NetQ30_1: Q30.1(B) Q30.3(C) R117.1
NetQ31_1: Q31.1(B) Q31.3(C) R118.1
NetR112_1: R112.1 R128.2 Sensor1.2
NetR113_1: R113.1 R130.2 Sensor2.2
NetR114_1: R114.1 R132.2 Sensor3.2

Not connected (* = marked no-connect by the designer): U23 8(~{THERM})* 9(~{THERM2})*

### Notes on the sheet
- (near U23) 600uA

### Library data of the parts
C114 = CMP-0006861-3: CAP, CERM, 0.1 uF, 50 V, +/- 10%, X7R, 0603; Manufacturer: Kemet; TaMin_C: -55°C; Polarized: N; SizeAreaWB_mm2: 4.68; Value1: Unknown; U/M: EA; Value: 0.1uF; TaMax_C: 125°C; SizeZ_mm: 1; SizeX_mm: 1.6; SizeY_mm: 0.8; SizeArea_mm2: 1.28; AEC Category: Q200
C115-C121 C156 = CMP-0006843-4: CAP, CERM, 1000 pF, 50 V, +/- 5%, C0G/NP0, 0603; Manufacturer: Kemet; TaMin_C: -55°C; Polarized: N; SizeAreaWB_mm2: 4.68; Value1: Unknown; U/M: EA; Value: 1000pF; TaMax_C: 125°C; SizeZ_mm: 1; SizeX_mm: 1.6; SizeY_mm: 0.8; SizeArea_mm2: 1.28; Cap_F: 1nF; AEC Category: Q200
I2C_pull Sensor1-Sensor3 = CMP-0075049-1: as J_heater on sheet MCU_ADC
Q11 Q25-Q31 = CMP-0000409-2: Transistor, NPN, 40 V, 0.2 A, 3-UFDFN; Manufacturer: Diodes Inc.; TaMax_C: 150°C; Value2: 400; Value1: 0.2 A; Vcesat1_V: 300mV; SizeX_mm: 1; SizeY_mm: 0.6; TaMin_C: -55°C; IcRated_A: 200mA; CompType: BJT; SizeZ_mm: 0.53; Value: 40 V; Vceo_V: 40V; PNP: 0; AEC Category: Q101; SizeAreaWB_mm2: 3.2; U/M: EA
R6 R112-R118 = CMP-0023919-1: RES, 1.00 k, 0.1%, 0.1 W, 0603; Manufacturer: Yageo America; Power_W: 100mW; TempCo: 25 ppm/C; Value_Code: 1k00; U/M: EA; Value: 1.00k; EIA_Code: E192; Res_ohm: 1k; SizeX_mm: 1.6; SizeY_mm: 0.8; SizeZ_mm: 1; Value2: 0.1W; SizeArea_mm2: 1.28; VDC_V: 75V; AEC Category: Q200
R110 R111 = CMP-0020740-1: RES, 5.1 k, 5%, 0.125 W, 0805; Manufacturer: Panasonic; Power_W: 125mW; TempCo: 200 ppm/C; Value_Code: 5k10; U/M: EA; Value: 5.1k; EIA_Code: E24; SizeX_mm: 2; SizeY_mm: 1.25; SizeZ_mm: 1.45; Value2: 0.125W; SizeArea_mm2: 2.5; VDC_V: 150V; AEC Category: Q200
R128-R133 = CMP-0025884-1: RES, 0, 5%, 0.125 W, 0603; Manufacturer: Vishay/Beyschlag; Power_W: 125mW; TempCo: ppm/C; Value_Code: 0000; U/M: EA; Value: 0; EIA_Code: E24; SizeX_mm: 1.6; SizeY_mm: 0.8; SizeZ_mm: 1; Value2: 0.125W; SizeArea_mm2: 1.28; AEC Qualified: N; AEC Category: Q200
U23 = CMP-0097071-1: 9-Channel (8-Remote and 1-Local), High-Accuracy Temperature Sensor; Manufacturer: Texas Instruments; Standoff Height: 0.097mm; AEC Qualified: No; Sensor Output: I2C,SMBus; Min Supply Voltage: 1.7V; Accuracy: 2%; TaMax_C: +125°C; Interface: I2C,2-Wire,SMBus; TaMin_C: -55°C; SizeZ_mm: 2.227mm; Max Supply Voltage: 3.6V; TJmax_C: +150°C; Resolution: 13bits

## Sheet Monitor.SchDoc
size 431 x 279 mm; Date: Not shown in title block; ApprovedBy: Not shown in title block; CheckedBy: Not shown in title block; Author: Not shown in title block; CompanyName: Not shown in title block; Engineer: Not shown in title block; Organization: Not shown in title block; Address1: Not shown in title block; Address2: Not shown in title block; Address3: Not shown in title block; Address4: Not shown in title block; DocumentNumber: 1; Revision: Use project parameter SCH_Rev; SheetNumber: 8; SheetTotal: 8; PageSetup: Record=PageOptions¦CenterHorizontal=True¦CenterVertical=True¦PrintScale=1.00¦XCorrection=1.00¦YCorrection=1.00¦PrintKind=0¦BorderSize=5000000¦LeftOffset=0¦BottomOffset=0¦Orientation=2¦PaperLength=1000¦PaperWidth=1000¦Scale=100¦PaperSource=15¦PrintQuality=600¦MediaType=1¦DitherType=10¦PaperKind=Letter¦PrintScaleMode=1
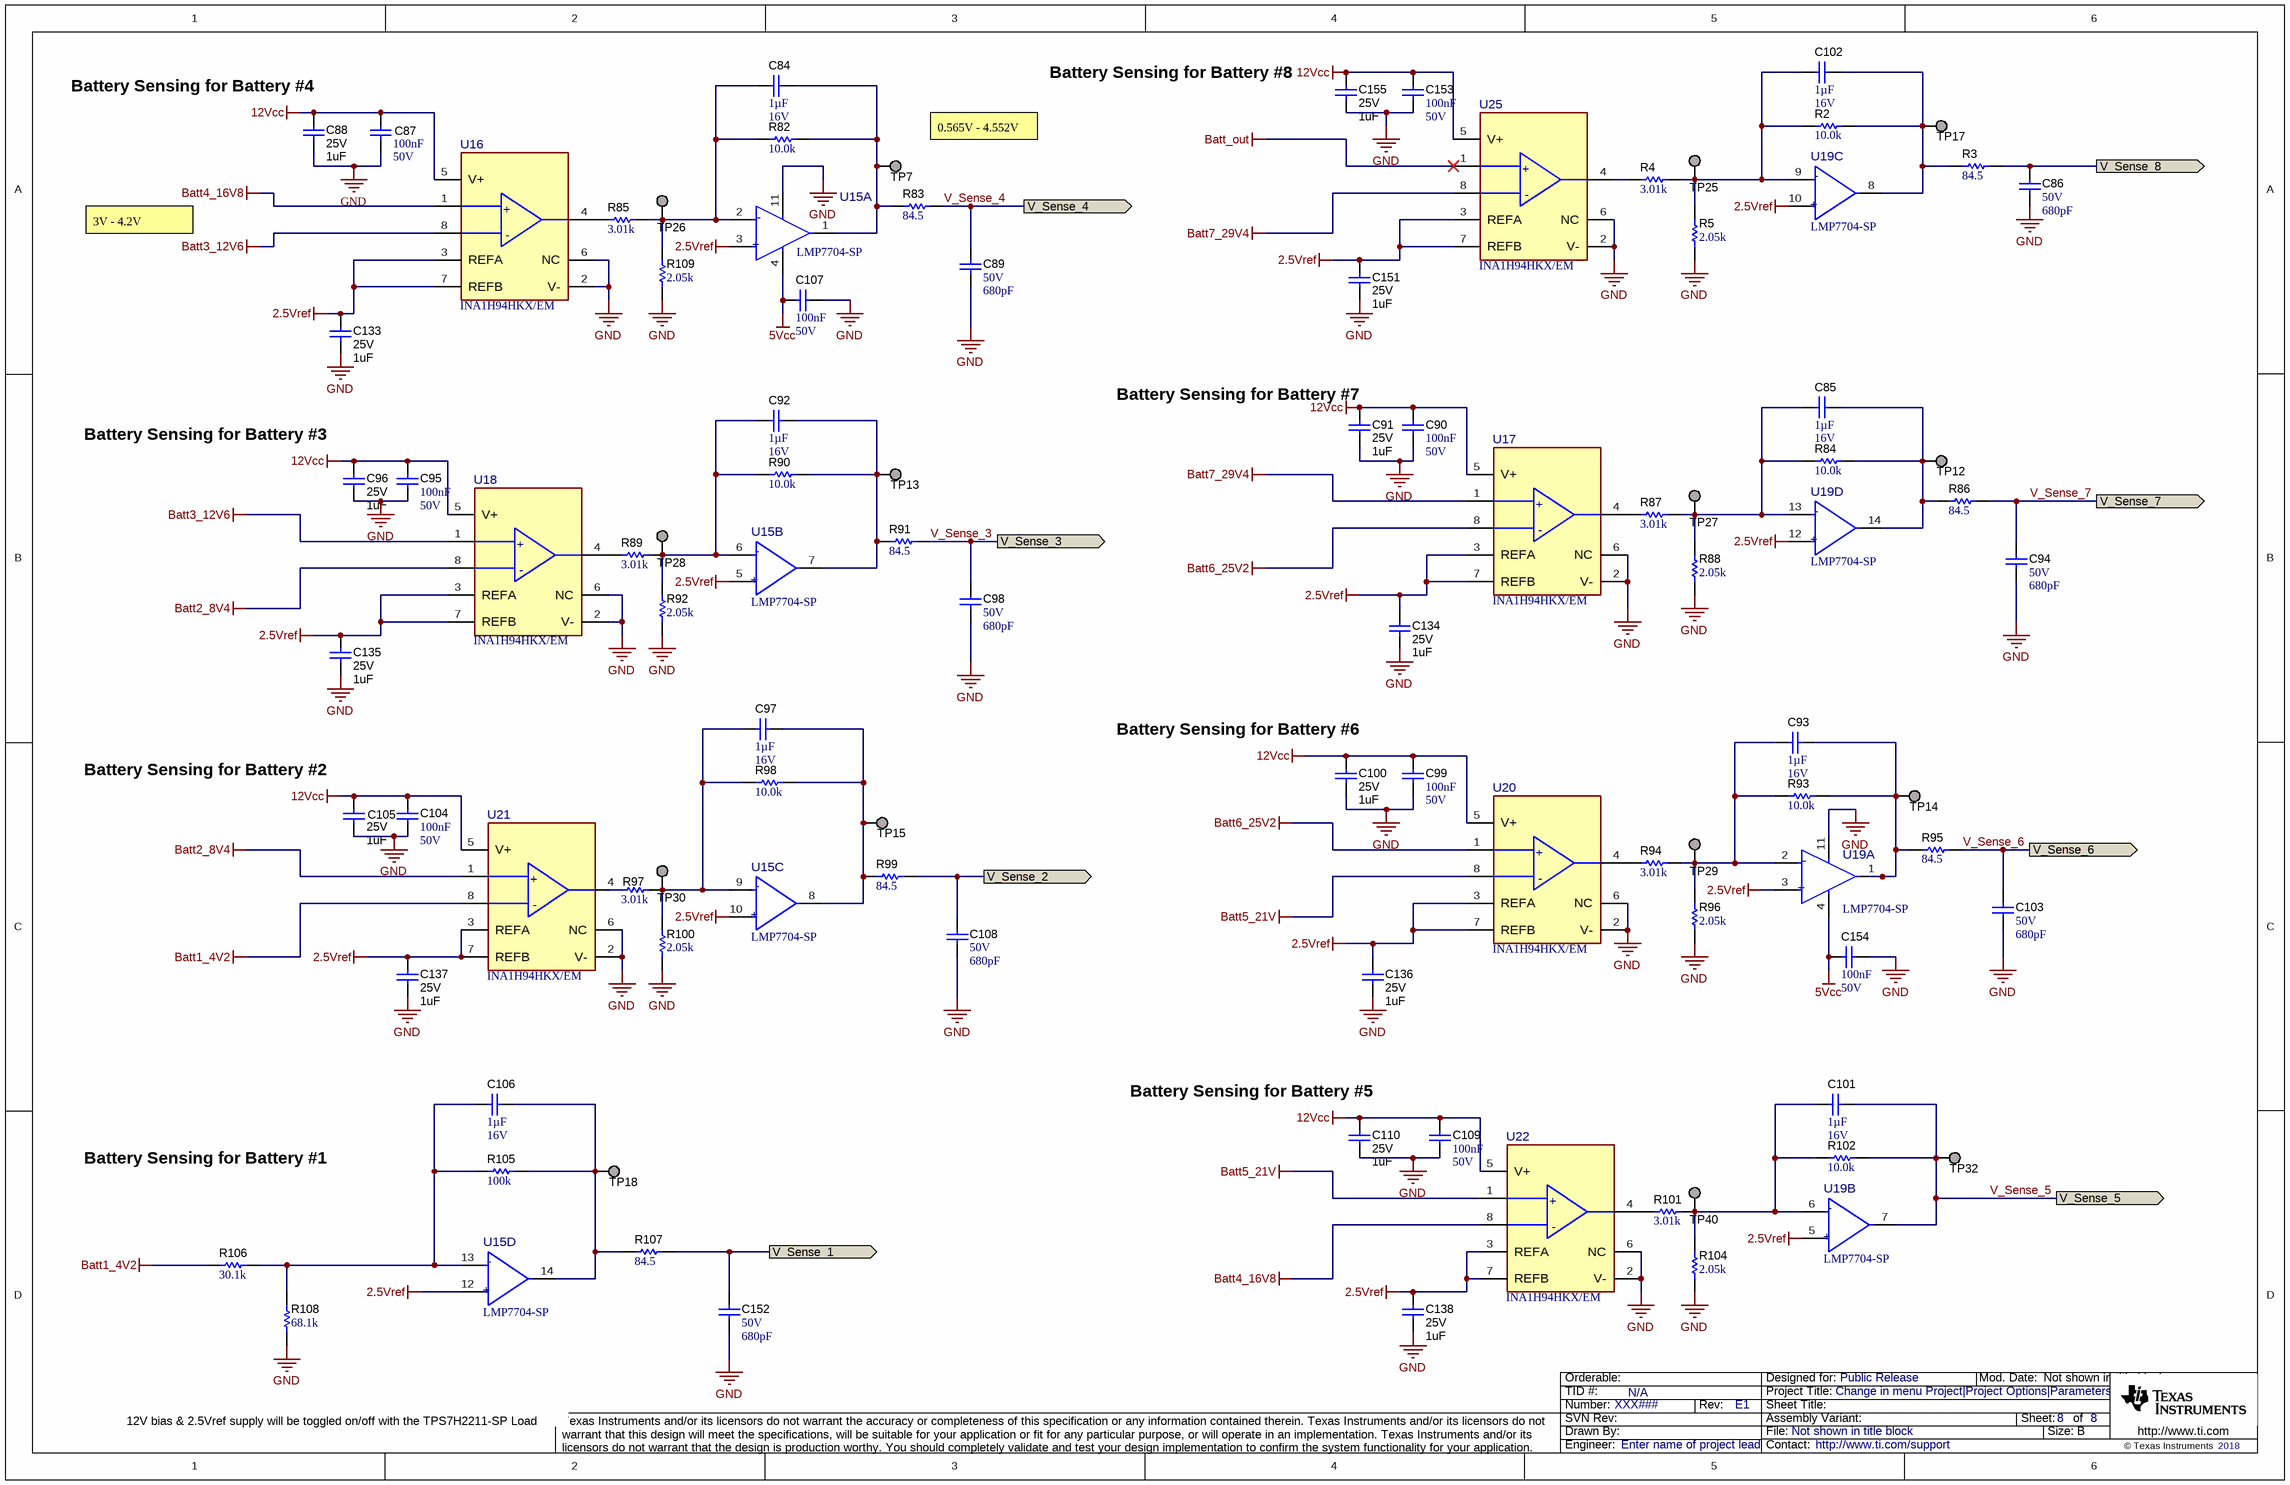
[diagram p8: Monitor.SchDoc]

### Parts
C84  Cap_F: 1µF  VDC_V: 16V  [0805_HV]  (hidden comment: GRM21BR71C105KA01L)
C85  Cap_F: 1µF  VDC_V: 16V  [0805_HV]  (hidden comment: GRM21BR71C105KA01L)
C86  VDC_V: 50V  ValueDisplayed: 680pF  [0603]  (hidden comment: 06035A681FAT2A)
C87  Cap_F: 100nF  VDC_V: 50V  [0603]  (hidden comment: CGA3E2X7R1H104K080AA)
C88  VDC_V: 25V  ValueDisplayed: 1uF  [0603]  (hidden comment: C1608X5R1E105K080AC)
C89  VDC_V: 50V  ValueDisplayed: 680pF  [0603]  (hidden comment: 06035A681FAT2A)
C90  Cap_F: 100nF  VDC_V: 50V  [0603]  (hidden comment: CGA3E2X7R1H104K080AA)
C91  VDC_V: 25V  ValueDisplayed: 1uF  [0603]  (hidden comment: C1608X5R1E105K080AC)
C92  Cap_F: 1µF  VDC_V: 16V  [0805_HV]  (hidden comment: GRM21BR71C105KA01L)
C93  Cap_F: 1µF  VDC_V: 16V  [0805_HV]  (hidden comment: GRM21BR71C105KA01L)
C94  VDC_V: 50V  ValueDisplayed: 680pF  [0603]  (hidden comment: 06035A681FAT2A)
C95  Cap_F: 100nF  VDC_V: 50V  [0603]  (hidden comment: CGA3E2X7R1H104K080AA)
C96  VDC_V: 25V  ValueDisplayed: 1uF  [0603]  (hidden comment: C1608X5R1E105K080AC)
C97  Cap_F: 1µF  VDC_V: 16V  [0805_HV]  (hidden comment: GRM21BR71C105KA01L)
C98  VDC_V: 50V  ValueDisplayed: 680pF  [0603]  (hidden comment: 06035A681FAT2A)
C99  Cap_F: 100nF  VDC_V: 50V  [0603L]  (hidden comment: CGA3E2X7R1H104K080AA)
C100  VDC_V: 25V  ValueDisplayed: 1uF  [0603]  (hidden comment: C1608X5R1E105K080AC)
C101  Cap_F: 1µF  VDC_V: 16V  [0805_HV]  (hidden comment: GRM21BR71C105KA01L)
C102  Cap_F: 1µF  VDC_V: 16V  [0805_HV]  (hidden comment: GRM21BR71C105KA01L)
C103  VDC_V: 50V  ValueDisplayed: 680pF  [0603]  (hidden comment: 06035A681FAT2A)
C104  Cap_F: 100nF  VDC_V: 50V  [0603]  (hidden comment: CGA3E2X7R1H104K080AA)
C105  VDC_V: 25V  ValueDisplayed: 1uF  [0603]  (hidden comment: C1608X5R1E105K080AC)
C106  Cap_F: 1µF  VDC_V: 16V  [0805_HV]  (hidden comment: GRM21BR71C105KA01L)
C107  Cap_F: 100nF  VDC_V: 50V  [0603]  (hidden comment: CGA3E2X7R1H104K080AA)
C108  VDC_V: 50V  ValueDisplayed: 680pF  [0603]  (hidden comment: 06035A681FAT2A)
C109  Cap_F: 100nF  VDC_V: 50V  [0603]  (hidden comment: CGA3E2X7R1H104K080AA)
C110  VDC_V: 25V  ValueDisplayed: 1uF  [0603]  (hidden comment: C1608X5R1E105K080AC)
C133  VDC_V: 25V  ValueDisplayed: 1uF  [0603L]  (hidden comment: C1608X5R1E105K080AC)
C134  VDC_V: 25V  ValueDisplayed: 1uF  [0603L]  (hidden comment: C1608X5R1E105K080AC)
C135  VDC_V: 25V  ValueDisplayed: 1uF  [0603]  (hidden comment: C1608X5R1E105K080AC)
C136  VDC_V: 25V  ValueDisplayed: 1uF  [0603L]  (hidden comment: C1608X5R1E105K080AC)
C137  VDC_V: 25V  ValueDisplayed: 1uF  [0603]  (hidden comment: C1608X5R1E105K080AC)
C138  VDC_V: 25V  ValueDisplayed: 1uF  [0603]  (hidden comment: C1608X5R1E105K080AC)
C151  VDC_V: 25V  ValueDisplayed: 1uF  [0603L]  (hidden comment: C1608X5R1E105K080AC)
C152  VDC_V: 50V  ValueDisplayed: 680pF  [0603]  (hidden comment: 06035A681FAT2A)
C153  Cap_F: 100nF  VDC_V: 50V  [0603]  (hidden comment: CGA3E2X7R1H104K080AA)
C154  Cap_F: 100nF  VDC_V: 50V  [0603]  (hidden comment: CGA3E2X7R1H104K080AA)
C155  VDC_V: 25V  ValueDisplayed: 1uF  [0603L]  (hidden comment: C1608X5R1E105K080AC)
R2  ValueDisplayed: 10.0k  [0805_HV]  (hidden comment: RG2012P-103-B-T5)
R3  ValueDisplayed: 84.5  [0603]  (hidden comment: RC0603FR-0784R5L)
R4  ValueDisplayed: 3.01k  [0805_HV]  (hidden comment: RT0805BRD073K01L)
R5  ValueDisplayed: 2.05k  [0805_HV]  (hidden comment: RT0805BRD072K05L)
R82  ValueDisplayed: 10.0k  [0805_HV]  (hidden comment: RG2012P-103-B-T5)
R83  ValueDisplayed: 84.5  [0603]  (hidden comment: RC0603FR-0784R5L)
R84  ValueDisplayed: 10.0k  [0805_HV]  (hidden comment: RG2012P-103-B-T5)
R85  ValueDisplayed: 3.01k  [0805_HV]  (hidden comment: RT0805BRD073K01L)
R86  ValueDisplayed: 84.5  [0603]  (hidden comment: RC0603FR-0784R5L)
R87  ValueDisplayed: 3.01k  [0805_HV]  (hidden comment: RT0805BRD073K01L)
R88  ValueDisplayed: 2.05k  [0805_HV]  (hidden comment: RT0805BRD072K05L)
R89  ValueDisplayed: 3.01k  [0805_HV]  (hidden comment: RT0805BRD073K01L)
R90  ValueDisplayed: 10.0k  [0805_HV]  (hidden comment: RG2012P-103-B-T5)
R91  ValueDisplayed: 84.5  [0603]  (hidden comment: RC0603FR-0784R5L)
R92  ValueDisplayed: 2.05k  [0805_HV]  (hidden comment: RT0805BRD072K05L)
R93  ValueDisplayed: 10.0k  [0805_HV]  (hidden comment: RG2012P-103-B-T5)
R94  ValueDisplayed: 3.01k  [0805_HV]  (hidden comment: RT0805BRD073K01L)
R95  ValueDisplayed: 84.5  [0603]  (hidden comment: RC0603FR-0784R5L)
R96  ValueDisplayed: 2.05k  [0805_HV]  (hidden comment: RT0805BRD072K05L)
R97  ValueDisplayed: 3.01k  [0805_HV]  (hidden comment: RT0805BRD073K01L)
R98  ValueDisplayed: 10.0k  [0805_HV]  (hidden comment: RG2012P-103-B-T5)
R99  ValueDisplayed: 84.5  [0603]  (hidden comment: RC0603FR-0784R5L)
R100  ValueDisplayed: 2.05k  [0805_HV]  (hidden comment: RT0805BRD072K05L)
R101  ValueDisplayed: 3.01k  [0805_HV]  (hidden comment: RT0805BRD073K01L)
R102  ValueDisplayed: 10.0k  [0805_HV]  (hidden comment: RG2012P-103-B-T5)
R104  ValueDisplayed: 2.05k  [0805_HV]  (hidden comment: RT0805BRD072K05L)
R105  ValueDisplayed: 100k  [0805_HV]  (hidden comment: RG2012P-104-B-T5)
R106  ValueDisplayed: 30.1k  [0805_HV]  (hidden comment: RT0805BRD0730K1L)
R107  ValueDisplayed: 84.5  [0603]  (hidden comment: RC0603FR-0784R5L)
R108  ValueDisplayed: 68.1k  [0805_HV]  (hidden comment: RT0805BRD0768K1L)
R109  ValueDisplayed: 2.05k  [0805_HV]  (hidden comment: RT0805BRD072K05L)
TP7  TP_SM_1MM  [TP_SM_1MM]  (value not drawn)  (no BOM)
TP12  TP_SM_1MM  [TP_SM_1MM]  (value not drawn)  (no BOM)
TP13  TP_SM_1MM  [TP_SM_1MM]  (value not drawn)  (no BOM)
TP14  TP_SM_1MM  [TP_SM_1MM]  (value not drawn)  (no BOM)
TP15  TP_SM_1MM  [TP_SM_1MM]  (value not drawn)  (no BOM)
TP17  TP_SM_1MM  [TP_SM_1MM]  (value not drawn)  (no BOM)
TP18  TP_SM_1MM  [TP_SM_1MM]  (value not drawn)  (no BOM)
TP25  TP_SM_1MM  [TP_SM_1MM]  (value not drawn)  (no BOM)
TP26  TP_SM_1MM  [TP_SM_1MM]  (value not drawn)  (no BOM)
TP27  TP_SM_1MM  [TP_SM_1MM]  (value not drawn)  (no BOM)
TP28  TP_SM_1MM  [TP_SM_1MM]  (value not drawn)  (no BOM)
TP29  TP_SM_1MM  [TP_SM_1MM]  (value not drawn)  (no BOM)
TP30  TP_SM_1MM  [TP_SM_1MM]  (value not drawn)  (no BOM)
TP32  TP_SM_1MM  [TP_SM_1MM]  (value not drawn)  (no BOM)
TP40  TP_SM_1MM  [TP_SM_1MM]  (value not drawn)  (no BOM)
U15  LMP7704-SP  [0-IPC_C]  (parts A,B,C,D of 4)
U16  INA1H94HKX/EM  [HKX0008A-IPC_C]
U17  INA1H94HKX/EM  [HKX0008A-IPC_C]
U18  INA1H94HKX/EM  [HKX0008A-IPC_C]
U19  LMP7704-SP  [0-IPC_C]  (parts A,B,C,D of 4)
U20  INA1H94HKX/EM  [HKX0008A-IPC_C]
U21  INA1H94HKX/EM  [HKX0008A-IPC_C]
U22  INA1H94HKX/EM  [HKX0008A-IPC_C]
U25  INA1H94HKX/EM  [HKX0008A-IPC_C]

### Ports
V_Sense_1 (out), V_Sense_2 (out), V_Sense_3 (out), V_Sense_4 (out), V_Sense_5 (out), V_Sense_6 (out), V_Sense_7 (out), V_Sense_8 (out)

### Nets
2.5Vref: C133.2 C134.1 C135.1 C136.1 C137.1 C138.1 C151.1 U15.3(IN_A+) U15.5(IN_B+) U15.10(IN_C+) U15.12(IN_D+) U16.3(REFA) U16.7(REFB) U17.3(REFA) U17.7(REFB) U18.3(REFA) U18.7(REFB) U19.3(IN_A+) U19.5(IN_B+) U19.10(IN_C+) U19.12(IN_D+) U20.3(REFA) U20.7(REFB) U21.3(REFA) U21.7(REFB) U22.3(REFA) U22.7(REFB) U25.3(REFA) U25.7(REFB)
5Vcc: C107.1 C154.1 U15.4(V+) U19.4(V+)
12Vcc: C87.2 C88.2 C90.2 C91.2 C95.2 C96.2 C99.2 C100.2 C104.2 C105.2 C109.2 C110.2 C153.2 C155.2 U16.5(V+) U17.5(V+) U18.5(V+) U20.5(V+) U21.5(V+) U22.5(V+) U25.5(V+)
Batt1_4V2: R106.1 U21.8(-IN)
Batt2_8V4: U18.8(-IN) U21.1(+IN)
Batt3_12V6: U16.8(-IN) U18.1(+IN)
Batt4_16V8: U16.1(+IN) U22.8(-IN)
Batt5_21V: U20.8(-IN) U22.1(+IN)
Batt6_25V2: U17.8(-IN) U20.1(+IN)
Batt7_29V4: U17.1(+IN) U25.8(-IN)
Batt_out: U25.1(+IN)
GND: C86.2 C87.1 C88.1 C89.2 C90.1 C91.1 C94.2 C95.1 C96.1 C98.2 C99.1 C100.1 C103.2 C104.1 C105.1 C107.2 C108.2 C109.1 C110.1 C133.1 C134.2 C135.2 C136.2 C137.2 C138.2 C151.2 C152.2 C153.1 C154.2 C155.1 R5.1 R88.1 R92.1 R96.1 R100.1 R104.1 R108.1 R109.1 U15.11(V-) U16.2(V-) U16.6(NC) U17.2(V-) U17.6(NC) U18.2(V-) U18.6(NC) U19.11(V-) U20.2(V-) U20.6(NC) U21.2(V-) U21.6(NC) U22.2(V-) U22.6(NC) U25.2(V-) U25.6(NC)
V_Sense_1: C152.1 R107.2 ; port V_Sense_1
V_Sense_2: C108.1 R99.2 ; port V_Sense_2
V_Sense_3: C98.1 R91.2 ; port V_Sense_3
V_Sense_4: C89.1 R83.2 ; port V_Sense_4
V_Sense_5: C101.1 R102.2 TP32.1 U19.7(OUT_B) ; port V_Sense_5
V_Sense_6: C103.1 R95.2 ; port V_Sense_6
V_Sense_7: C94.1 R86.2 ; port V_Sense_7
V_Sense_8: C86.1 R3.2 ; port V_Sense_8
NetC84_1: C84.1 R82.2 R83.1 TP7.1 U15.1(OUT_A)
NetC84_2: C84.2 R82.1 R85.2 R109.2 TP26.1 U15.2(IN_A-)
NetC85_1: C85.1 R84.2 R86.1 TP12.1 U19.14(OUT_D)
NetC85_2: C85.2 R84.1 R87.2 R88.2 TP27.1 U19.13(IN_D-)
NetC92_1: C92.1 R90.2 R91.1 TP13.1 U15.7(OUT_B)
NetC92_2: C92.2 R89.2 R90.1 R92.2 TP28.1 U15.6(IN_B-)
NetC93_1: C93.1 R93.2 R95.1 TP14.1 U19.1(OUT_A)
NetC93_2: C93.2 R93.1 R94.2 R96.2 TP29.1 U19.2(IN_A-)
NetC97_1: C97.1 R98.2 R99.1 TP15.1 U15.8(OUT_C)
NetC97_2: C97.2 R97.2 R98.1 R100.2 TP30.1 U15.9(IN_C-)
NetC101_2: C101.2 R101.2 R102.1 R104.2 TP40.1 U19.6(IN_B-)
NetC102_1: C102.1 R2.2 R3.1 TP17.1 U19.8(OUT_C)
NetC102_2: C102.2 R2.1 R4.2 R5.2 TP25.1 U19.9(IN_C-)
NetC106_1: C106.1 R105.2 R107.1 TP18.1 U15.14(OUT_D)
NetC106_2: C106.2 R105.1 R106.2 R108.2 U15.13(IN_D-)
NetR4_1: R4.1 U25.4(VOUT)
NetR85_1: R85.1 U16.4(VOUT)
NetR87_1: R87.1 U17.4(VOUT)
NetR89_1: R89.1 U18.4(VOUT)
NetR94_1: R94.1 U20.4(VOUT)
NetR97_1: R97.1 U21.4(VOUT)
NetR101_1: R101.1 U22.4(VOUT)

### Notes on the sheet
- (near C88) Battery Sensing for Battery #4
- (near C155) Battery Sensing for Battery #8
- 0.565V - 4.552V
- 3V - 4.2V
- (near C96) Battery Sensing for Battery #3
- (near C91) Battery Sensing for Battery #7
- (near C105) Battery Sensing for Battery #2
- (near C100) Battery Sensing for Battery #6
- (near C110) Battery Sensing for Battery #5
- Battery Sensing for Battery #1
- 12V bias & 2.5Vref supply will be toggled on/off with the TPS7H2211-SP Load Switch

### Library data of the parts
C84 C85 C92 C93 C97 C101 C102 C106 = CMP-0008323-2: CAP, CERM, 1 uF, 16 V, +/- 10%, X7R, 0805; Manufacturer: MuRata; TaMin_C: -55°C; ESR_ohm: 3m; Polarized: N; SizeAreaWB_mm2: 6.75; Value1: 0.003 ohm; U/M: EA; Value: 1uF; TaMax_C: 125°C; SizeZ_mm: 1.45; SizeX_mm: 2; SizeY_mm: 1.25; Cap_Case: 0805; SizeArea_mm2: 2.5; AEC Category: Q200
C86 C89 C94 C98 C103 C108 C152 = CMP-0006797-3: as C111 on sheet MCU_ADC
C87 C90 C95 C104 C107 C109 C153 C154 = CMP-0007078-4: CAP, CERM, 0.1 uF, 50 V, +/- 10%, X7R, AEC-Q200 Grade 1, 0603; Manufacturer: TDK; TaMin_C: -55°C; ESR_ohm: 0.0296; Polarized: N; SizeAreaWB_mm2: 4.68; Value1: 0.0296 ohm; U/M: EA; Value: 0.1uF; TaMax_C: 125°C; SizeZ_mm: 1; SizeX_mm: 1.6; SizeY_mm: 0.8; SizeArea_mm2: 1.28; AEC Qualified: Y; IRMS_A: 971.99mA; AEC Category: Q200
C88 C91 C96 C100 C105 C110 C135 C137 C138 = CMP-0007006-2: CAP, CERM, 1 uF, 25 V, +/- 10%, X5R, 0603; Manufacturer: TDK; TaMin_C: -55°C; Polarized: N; SizeAreaWB_mm2: 4.68; Value1: Unknown; U/M: EA; Value: 1uF; TaMax_C: 85°C; SizeZ_mm: 1; SizeX_mm: 1.6; SizeY_mm: 0.8; SizeArea_mm2: 1.28; Cap_F: 1µF; AEC Category: Q200
C99 = CMP-0007078-4: CAP, CERM, 0.1 uF, 50 V, +/- 10%, X7R, AEC-Q200 Grade 1, 0603; Manufacturer: TDK; TaMin_C: -55°C; ESR_ohm: 0.0296; Polarized: N; SizeAreaWB_mm2: 4.68; Value1: 0.0296 ohm; U/M: EA; Value: 0.1uF; TaMax_C: 125°C; SizeZ_mm: 1; SizeX_mm: 1.6; SizeY_mm: 0.8; Cap_Case: 0603; SizeArea_mm2: 1.28; AEC Qualified: Y; IRMS_A: 971.99mA; AEC Category: Q200
C133 C134 C136 C151 C155 = CMP-0007006-2: CAP, CERM, 1 uF, 25 V, +/- 10%, X5R, 0603; Manufacturer: TDK; TaMin_C: -55°C; Polarized: N; SizeAreaWB_mm2: 4.68; Value1: Unknown; U/M: EA; Value: 1uF; TaMax_C: 85°C; SizeZ_mm: 1; SizeX_mm: 1.6; SizeY_mm: 0.8; Cap_Case: 0603; SizeArea_mm2: 1.28; Cap_F: 1µF; AEC Category: Q200
R2 R82 R84 R90 R93 R98 R102 = CMP-0018856-2: as R141 on sheet MCU_ADC
R3 R83 R86 R91 R95 R99 R107 = CMP-0023298-5: as R103 on sheet MCU_ADC
R4 R85 R87 R89 R94 R97 R101 = CMP-0020028-2: RES, 3.01 k, 0.1%, 0.125 W, 0805; Manufacturer: Yageo America; Power_W: 125mW; TempCo: 25 ppm/C; Value_Code: 3k01; U/M: EA; Value: 3.01k; EIA_Code: E192; SizeX_mm: 2; SizeY_mm: 1.25; SizeZ_mm: 1.45; Value2: 0.125W; SizeArea_mm2: 2.5; VDC_V: 150V; AEC Category: Q200
R5 R88 R92 R96 R100 R104 R109 = CMP-0019899-2: RES, 2.05 k, 0.1%, 0.125 W, 0805; Manufacturer: Yageo America; Power_W: 125mW; TempCo: 25 ppm/C; Value_Code: 2k05; U/M: EA; Value: 2.05k; EIA_Code: E192; SizeX_mm: 2; SizeY_mm: 1.25; SizeZ_mm: 1.45; Value2: 0.125W; SizeArea_mm2: 2.5; VDC_V: 150V; AEC Category: Q200
R105 = CMP-0018857-2: as R124 on sheet MCU_ADC
R106 = CMP-0019938-2: RES, 30.1 k, 0.1%, 0.125 W, 0805; Manufacturer: Yageo America; Power_W: 125mW; TempCo: 25 ppm/C; Value_Code: 30k1; U/M: EA; Value: 30.1k; EIA_Code: E192; SizeX_mm: 2; SizeY_mm: 1.25; SizeZ_mm: 1.45; Value2: 0.125W; SizeArea_mm2: 2.5; VDC_V: 150V; AEC Category: Q200
R108 = CMP-0020263-2: RES, 68.1 k, 0.1%, 0.125 W, 0805; Manufacturer: Yageo America; Power_W: 125mW; TempCo: 25 ppm/C; Value_Code: 68k1; U/M: EA; Value: 68.1k; EIA_Code: E192; SizeX_mm: 2; SizeY_mm: 1.25; SizeZ_mm: 1.45; Value2: 0.125W; SizeArea_mm2: 2.5; VDC_V: 150V; AEC Category: Q200
TP7 TP12-TP15 TP17 TP18 TP25-TP30 TP32 TP40 = CMP-0003825-1: 1mm Test Point, SMT; Manufacturer: Any
U15 U19 = CMP-0089209-1: Precision, CMOS Input, RRIO, Wide Supply Range Amplifiers; Manufacturer: Texas Instruments; Min Supply Voltage: 2.7V; TJmax_C: +150°C; Standoff Height: 0.008inch; Output Current Per Channel: 42-84mA; SizeZ_mm: 0.111inch; Number Of Channels: 4; Max Dual Supply Voltage: 12V; Voltage Gain: 134dB; Nominal Supply Current: 4.5-4.6mA; Gain Bandwidth: 2.5MHz; Input Bias Current: 0.0000002uA; Input Offset Voltage: 0.037mV; AEC Qualified: No
U16-U18 U20-U22 U25 = CMP-0096976-1: Radiation-Hardened, High Common-Mode Voltage Difference Amplifier; Manufacturer: Texas Instruments; Number Of Channels: 1; Nominal Supply Current: 810uA; Output Current Per Channel: 25mA; TJmax_C: +150°C; Max Dual Supply Voltage: 9V; Response Time: 7us; Voltage Gain: 0.001V/mV; Min Dual Supply Voltage: 2V; Input Offset Voltage: 0.35mV; Max Supply Voltage: 18V; TaMin_C: -55°C; Bandwidth: 500kHz; SizeZ_mm: 2.785mm; AEC Qualified: No; Min Supply Voltage: 4V

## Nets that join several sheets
1.89V: Power Tree (J_1V85.1), Temp Sensing (C114.2 U23.12)
2.5Vref: Power Tree (14 pins), MCU_ADC (J5.1), Monitor (29 pins)
3.3V: Batt_Stack_Control (NMOS) (19 pins), Power Tree (J_3V3.2 Q42.2 R21.2), MCU_ADC (5 pins)
3.3V_2: Power Tree (J_3V3_2.2), MCU_ADC (C7.1 C8.1 U2.13), Temp Sensing (I2C_pull.1)
5Vcc: Batt_Stack_Control (NMOS) (12 pins), Power Tree (7 pins), MCU_ADC (C5.1 C6.1 U2.2), Monitor (C107.1 C154.1 U15.4 U19.4)
12Vcc: Batt_Stack_Control (NMOS) (J4.3), Power Tree (9 pins), Monitor (21 pins)
Batt1_4V2: Balancer (6 pins), Monitor (R106.1 U21.8)
Batt2_8V4: Balancer (7 pins), Monitor (U18.8 U21.1)
Batt3_12V6: Balancer (7 pins), Monitor (U16.8 U18.1)
Batt4_16V8: Balancer (7 pins), Monitor (U16.1 U22.8)
Batt5_21V: Balancer (7 pins), Monitor (U20.8 U22.1)
Batt6_25V2: Balancer (7 pins), Monitor (U17.8 U20.1)
Batt7_29V4: Balancer (7 pins), Monitor (U17.1 U25.8)
Batt_out: Batt_Stack_Control (NMOS) (5 pins), Power Tree (C24.1 U5.1), MCU_ADC (R124.2), Balancer (5 pins), Monitor (U25.1)
Charger_Vin: Batt_Stack_Control (NMOS) (7 pins), MCU_ADC (R140.2)
GND: Batt_Stack_Control (NMOS) (53 pins), Power Tree (63 pins), MCU_ADC (24 pins), Balancer (10 pins), Temp Sensing (C114.1 U23.6 U23.7), Monitor (54 pins)
2V5_EN: Power Tree (Q37.1 Q41.1), MCU_ADC (U1.6)
3V3_EN: Power Tree (C164.2 Q42.1 R21.1), MCU_ADC (U1.28)
12V_EN: Power Tree (U3.6), MCU_ADC (U1.29)
BAL1_MCU: MCU_ADC (U1.10), Balancer (R75.2)
BAL2_MCU: MCU_ADC (U1.9), Balancer (Q15.1)
BAL3_MCU: MCU_ADC (U1.8), Balancer (Q10.1)
BAL4_MCU: MCU_ADC (U1.7), Balancer (Q6.1)
BAL5_MCU: MCU_ADC (U1.5), Balancer (Q3.1)
BAL6_MCU: MCU_ADC (U1.4), Balancer (Q13.1)
BAL7_MCU: MCU_ADC (U1.3), Balancer (Q8.1)
BAL8_MCU: MCU_ADC (U1.2), Balancer (Q4.1)
FlipFlop GPIO4: Batt_Stack_Control (NMOS) (Q44.1), MCU_ADC (U1.33)
G1_on_off: Batt_Stack_Control (NMOS) (Q40.1), MCU_ADC (U1.34)
G2_on_off: Batt_Stack_Control (NMOS) (Q46.1), MCU_ADC (U1.35)
G3_on_off: Batt_Stack_Control (NMOS) (Q47.1), MCU_ADC (U1.30)
Load_good: Batt_Stack_Control (NMOS) (Q50.3 R63.1), MCU_ADC (U1.27)
PWM_10k: Batt_Stack_Control (NMOS) (R1.2), MCU_ADC (U1.1)
TEMP_SCL: MCU_ADC (J6.2 U1.32), Temp Sensing (R110.1 U23.11)
TEMP_SDA: MCU_ADC (J6.1 U1.31), Temp Sensing (R111.1 U23.10)
V_Sense_1: MCU_ADC (U2.11), Monitor (C152.1 R107.2)
V_Sense_2: MCU_ADC (U2.10), Monitor (C108.1 R99.2)
V_Sense_3: MCU_ADC (U2.9), Monitor (C98.1 R91.2)
V_Sense_4: MCU_ADC (U2.8), Monitor (C89.1 R83.2)
V_Sense_5: MCU_ADC (J5.3), Monitor (C101.1 R102.2 TP32.1 U19.7)
V_Sense_6: MCU_ADC (U2.6), Monitor (C103.1 R95.2)
V_Sense_7: MCU_ADC (U2.5), Monitor (C94.1 R86.2)
V_Sense_8: MCU_ADC (U2.4), Monitor (C86.1 R3.2)

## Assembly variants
001: not fitted C3 C4 C124 C125 D7 D10 FID1 FID2 FID3 Y1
